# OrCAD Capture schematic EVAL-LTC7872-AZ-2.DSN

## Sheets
1 PAGE1: size C; note: HIGH POWER POLY-PHASE BI-DIRECTIONAL SUPPLY/CHARGER
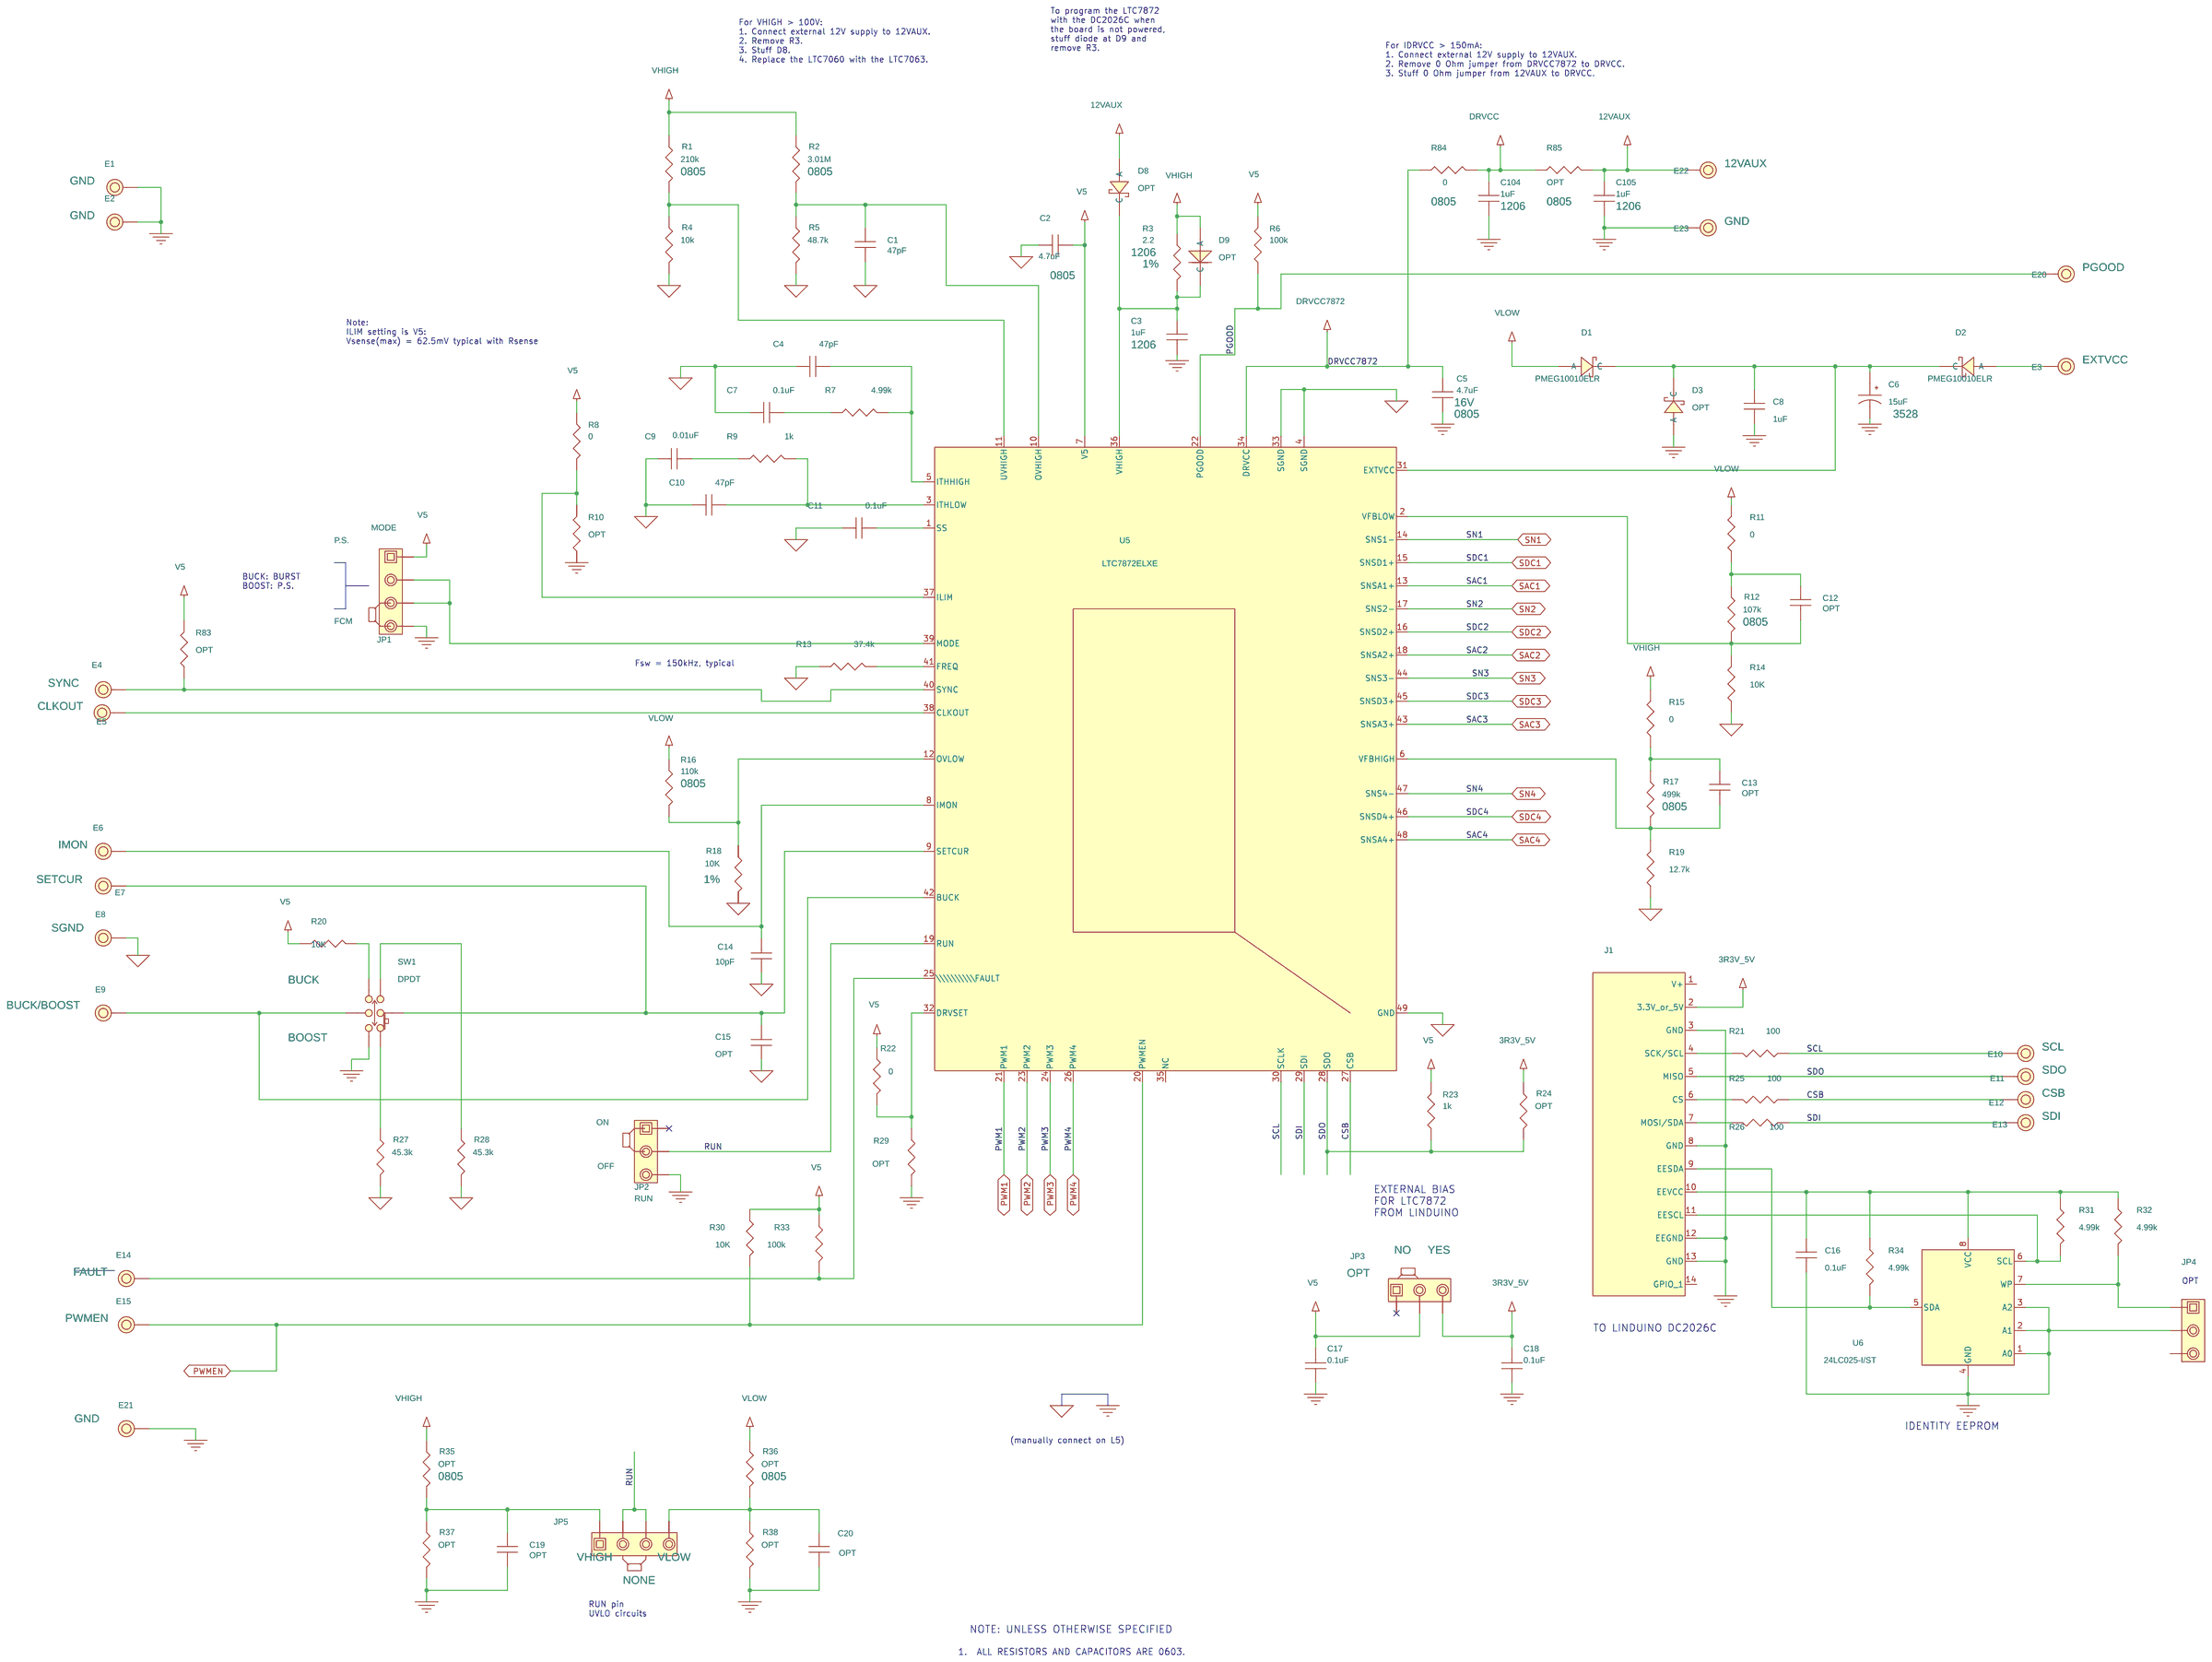
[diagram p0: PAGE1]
2 PAGE2: size Custom
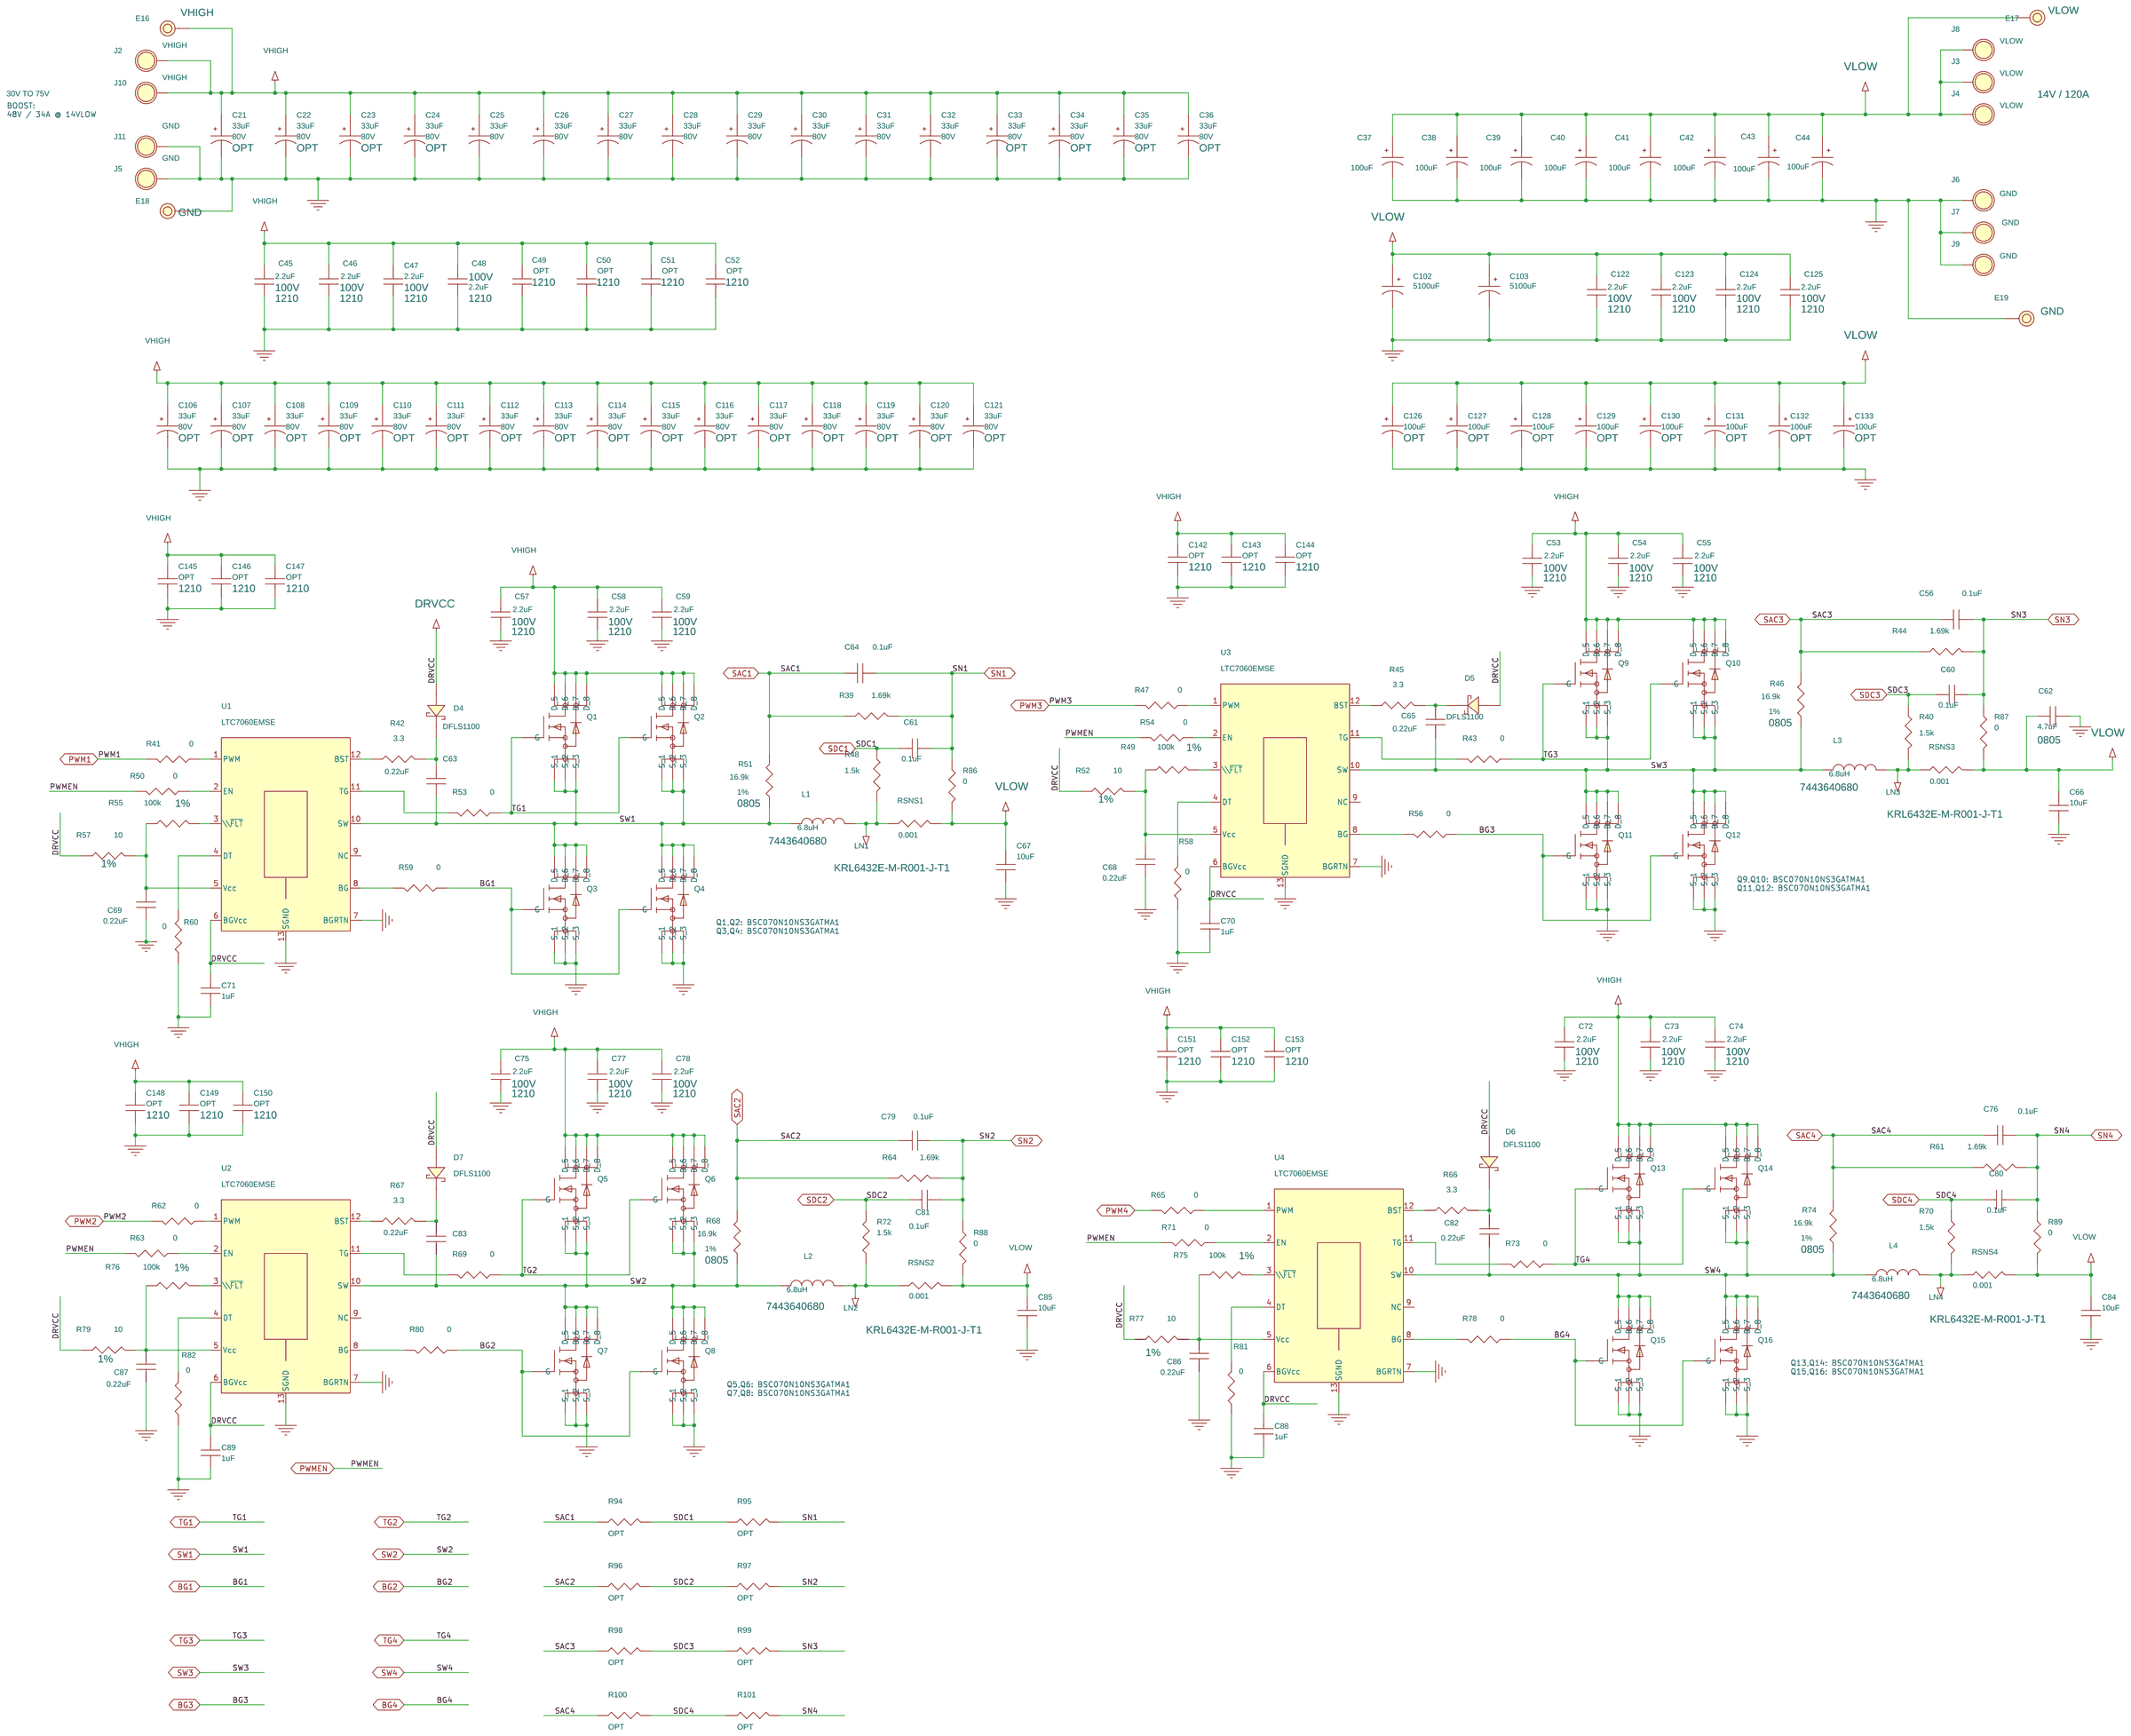
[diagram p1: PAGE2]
3 PAGE3: size B
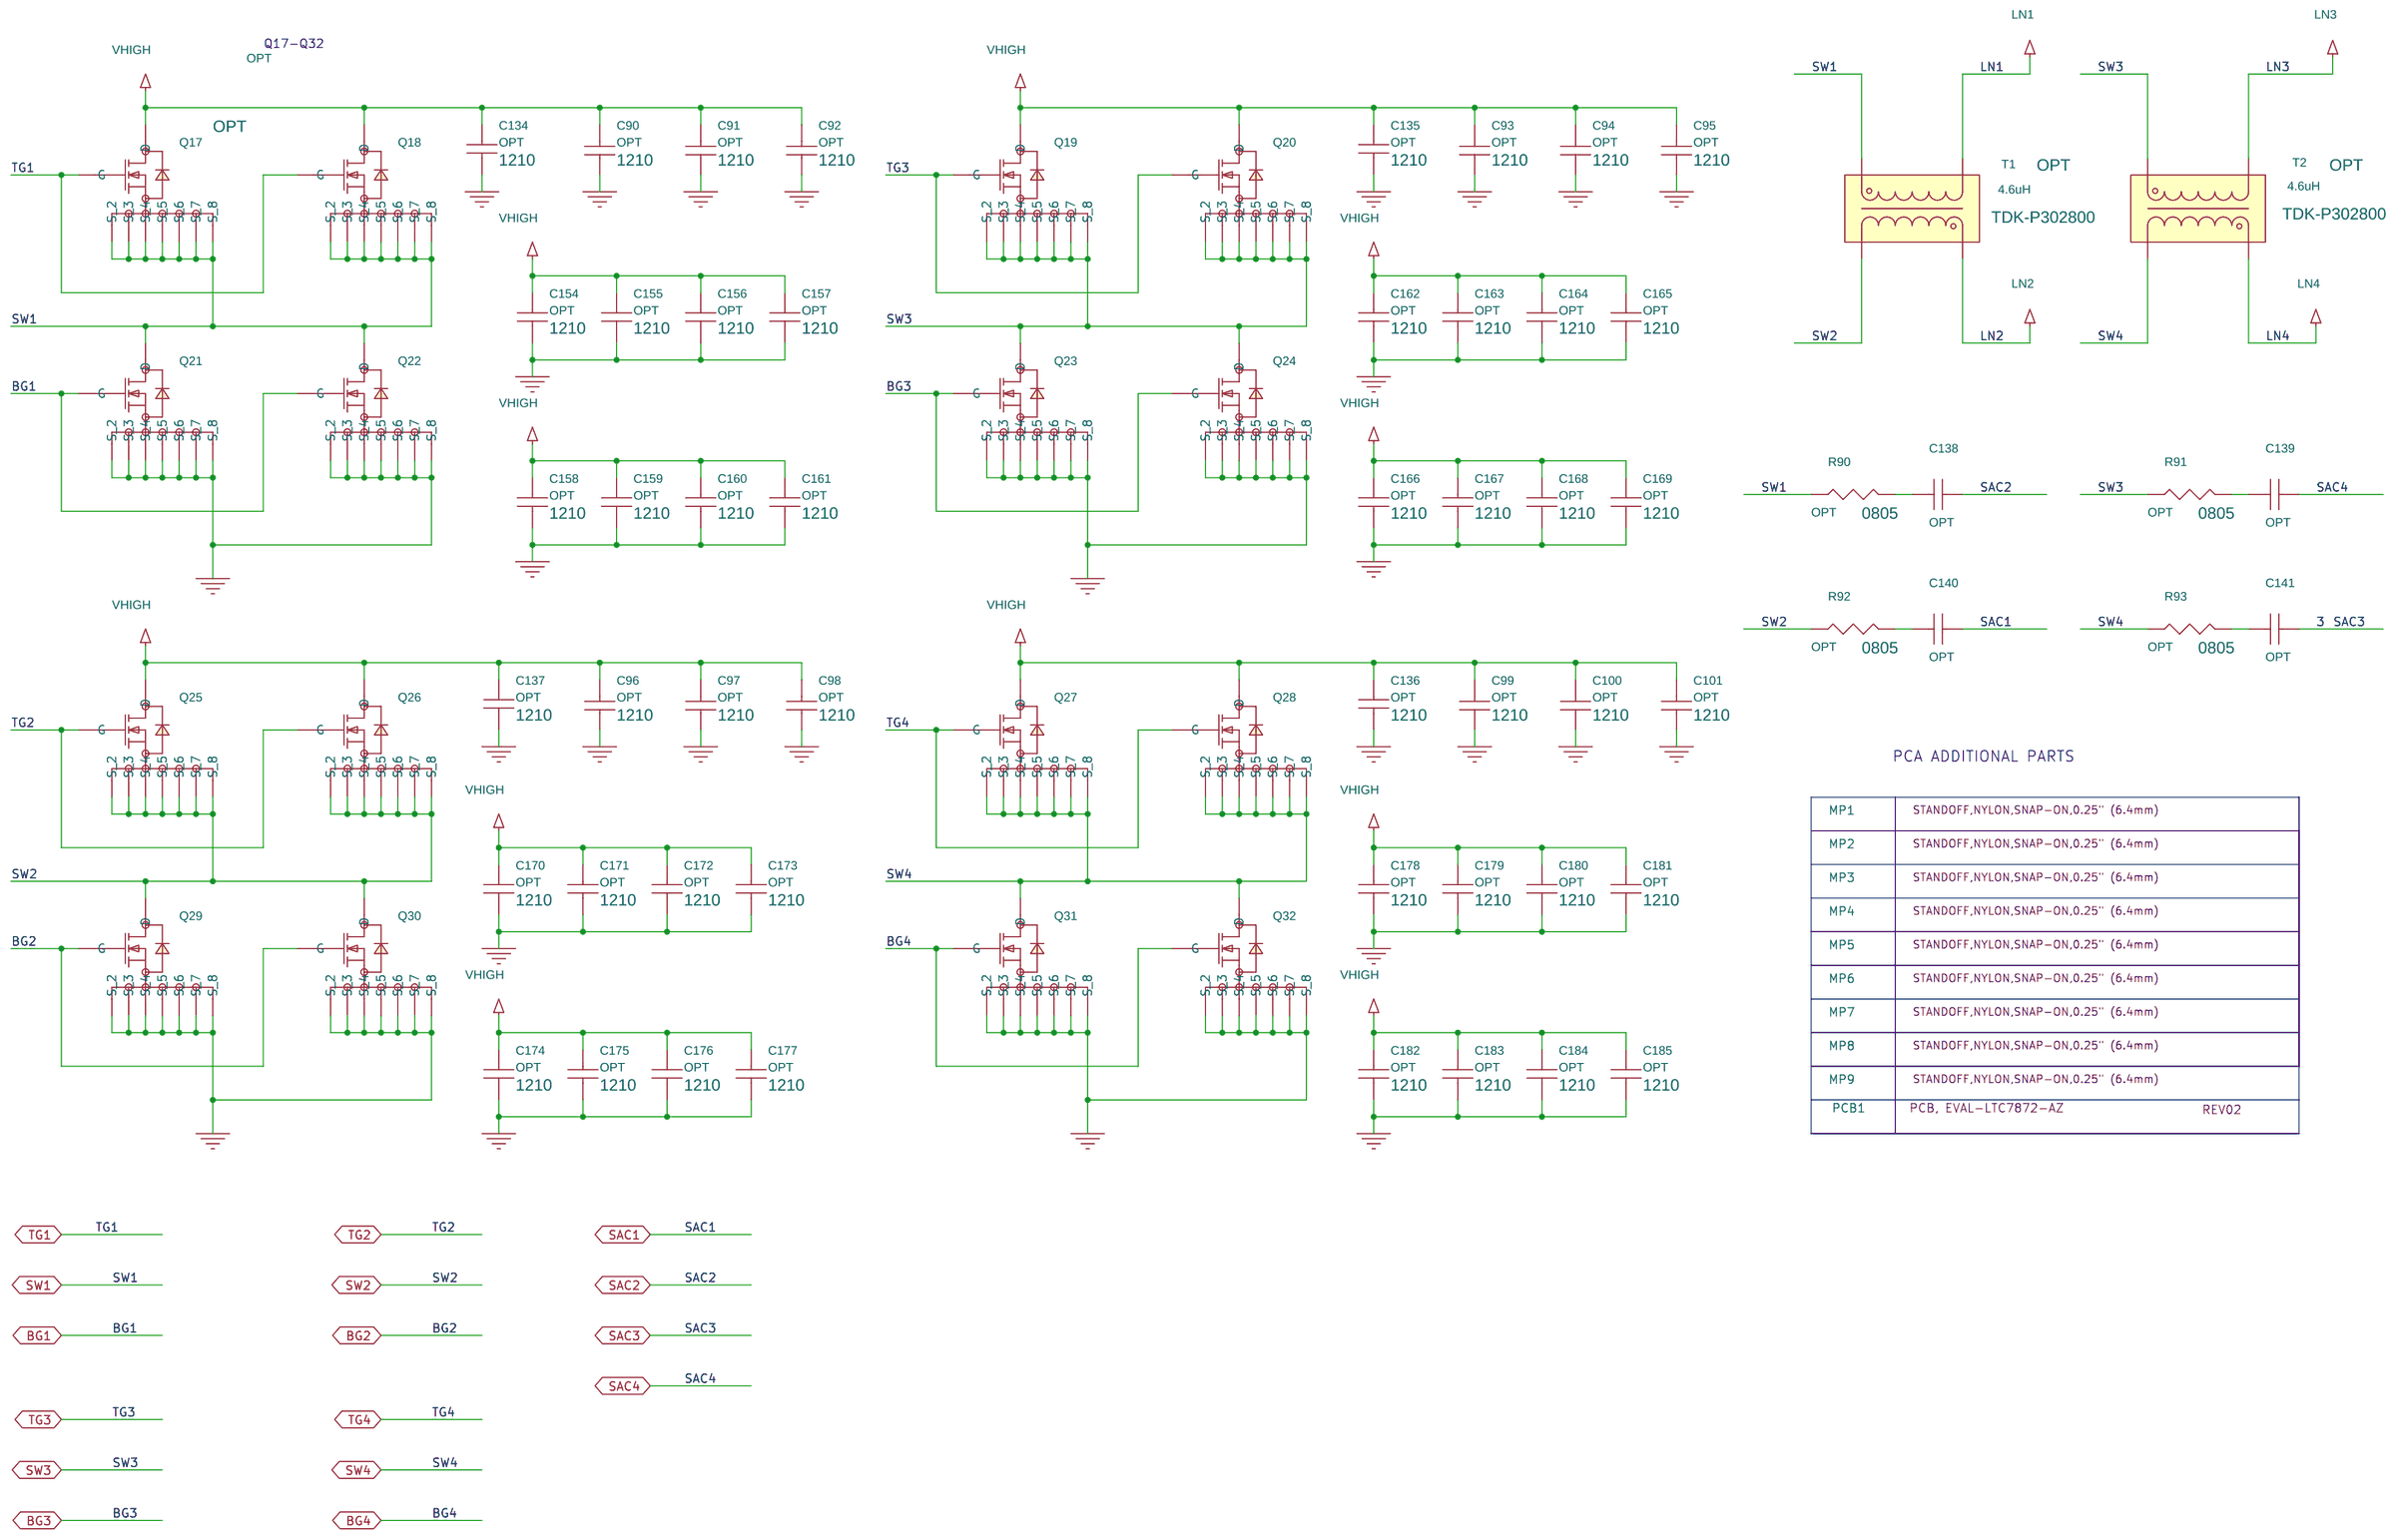
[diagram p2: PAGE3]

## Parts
sheet PAGE1
C1  47pF  [CC0603N]
C2  4.7uF  [CC0805N]
C3  1uF  [CC1206N]
C4  47pF  [CC0603N]
C5  4.7uF  [CC0805N]
C6  15uF  [CAPMP3528N]
C7  0.1uF  [CC0603N]
C8  1uF  [CC0603N]
C9  0.01uF  [CC0603N]
C10  47pF  [CC0603N]
C11  0.1uF  [CC0603N]
C12  OPT  [CC0603N]
C13  OPT  [CC0603N]
C14  10pF  [CC0603N]
C15  OPT  [CC0603N]
C16  0.1uF  [CC0603N]
C17  0.1uF  [CC0603N]
C18  0.1uF  [CC0603N]
C19  OPT  [CC0603N]
C20  OPT  [CC0603N]
C104  1uF  [CC1206N]
C105  1uF  [CC1206N]
D1  PMEG10010ELR  [NXP-SOD-123W]
D2  PMEG10010ELR  [NXP-SOD-123W]
D3  OPT  [SOD-323F-N]
D8  OPT  [SOD-323F-N]
D9  OPT  [SOD-123N]
E1  TEST POINT  [MILLMAX2501]
E2  TEST POINT  [MILLMAX2501]
E3  TEST POINT  [MILLMAX2501]
E4  TEST POINT  [MILLMAX2501]
E5  TEST POINT  [MILLMAX2501]
E6  TEST POINT  [MILLMAX2501]
E7  TEST POINT  [MILLMAX2501]
E8  TEST POINT  [MILLMAX2501]
E9  TEST POINT  [MILLMAX2501]
E10  TEST POINT  [MILLMAX2501]
E11  TEST POINT  [MILLMAX2501]
E12  TEST POINT  [MILLMAX2501]
E13  TEST POINT  [MILLMAX2501]
E14  TEST POINT  [MILLMAX2501]
E15  TEST POINT  [MILLMAX2501]
E20  TEST POINT  [MILLMAX2501]
E21  TEST POINT  [MILLMAX2501]
E22  TEST POINT  [MILLMAX2501]
E23  TEST POINT  [MILLMAX2501]
J1  HDR,SHROUDED  [HD2X7-079-MOLEX]
JP1  HDR  [HD1X4-079]
JP2  HDR  [HD1X3-079]
JP3  OPT  [HD1X3-079]
JP4  HDR  [HD1X3-079]
JP5  HDR  [HD1X4-079]
R1  210k  [CR0805N]
R2  3.01M  [CR0805N]
R3  2.2  [CR1206N]
R4  10k  [CR0603N]
R5  48.7k  [CR0603N]
R6  100k  [CR0603N]
R7  4.99k  [CR0603N]
R8  0  [CR0603N]
R9  1k  [CR0603N]
R10  OPT  [CR0603N]
R11  0  [CR0603N]
R12  107k  [CR0805N]
R13  37.4k  [CR0603N]
R14  10K  [CR0603N]
R15  0  [CR0603N]
R16  110k  [CR0805N]
R17  499k  [CR0805N]
R18  10K  [CR0603N]
R19  12.7k  [CR0603N]
R20  10K  [CR0603N]
R21  100  [CR0603N]
R22  0  [CR0603N]
R23  1k  [CR0603N]
R24  OPT  [CR0603N]
R25  100  [CR0603N]
R26  100  [CR0603N]
R27  45.3k  [CR0603N]
R28  45.3k  [CR0603N]
R29  OPT  [CR0603N]
R30  10K  [CR0603N]
R31  4.99k  [CR0603N]
R32  4.99k  [CR0603N]
R33  100k  [CR0603N]
R34  4.99k  [CR0603N]
R35  OPT  [CR0805N]
R36  OPT  [CR0805N]
R37  OPT  [CR0603N]
R38  OPT  [CR0603N]
R83  OPT  [CR0603N]
R84  0  [CR0805N]
R85  OPT  [CR0805N]
SW1  DPDT  [CK-JS202011CQN]
U5  LTC7872ELXE  [LXE-LQFP-48-1832]
U6  24LC025-I/ST  [MO-153AA_N]
XJP1  SHUNT  [SAMTEC-SHUNT-079]
XJP2  SHUNT  [SAMTEC-SHUNT-079]
XJP3  SHUNT  [SAMTEC-SHUNT-079]
XJP5  SHUNT  [SAMTEC-SHUNT-079]
sheet PAGE2
C21  33uF  [PANASONIC_ZC_10X10.2]
C22  33uF  [PANASONIC_ZC_10X10.2]
C23  33uF  [PANASONIC_ZC_10X10.2]
C24  33uF  [PANASONIC_ZC_10X10.2]
C25  33uF  [PANASONIC_ZC_10X10.2]
C26  33uF  [PANASONIC_ZC_10X10.2]
C27  33uF  [PANASONIC_ZC_10X10.2]
C28  33uF  [PANASONIC_ZC_10X10.2]
C29  33uF  [PANASONIC_ZC_10X10.2]
C30  33uF  [PANASONIC_ZC_10X10.2]
C31  33uF  [PANASONIC_ZC_10X10.2]
C32  33uF  [PANASONIC_ZC_10X10.2]
C33  33uF  [PANASONIC_ZC_10X10.2]
C34  33uF  [PANASONIC_ZC_10X10.2]
C35  33uF  [PANASONIC_ZC_10X10.2]
C36  33uF  [PANASONIC_ZC_10X10.2]
C37  100uF  [PANASONIC_ZA_6.3X7.7]
C38  100uF  [PANASONIC_ZA_6.3X7.7]
C39  100uF  [PANASONIC_ZA_6.3X7.7]
C40  100uF  [PANASONIC_ZA_6.3X7.7]
C41  100uF  [PANASONIC_ZA_6.3X7.7]
C42  100uF  [PANASONIC_ZA_6.3X7.7]
C43  100uF  [PANASONIC_ZA_6.3X7.7]
C44  100uF  [PANASONIC_ZA_6.3X7.7]
C45  2.2uF  [CC1210N]
C46  2.2uF  [CC1210N]
C47  2.2uF  [CC1210N]
C48  2.2uF  [CC1210N]
C49  OPT  [CC1210N]
C50  OPT  [CC1210N]
C51  OPT  [CC1210N]
C52  OPT  [CC1210N]
C53  2.2uF  [CC1210N]
C54  2.2uF  [CC1210N]
C55  2.2uF  [CC1210N]
C56  0.1uF  [CC0603N]
C57  2.2uF  [CC1210N]
C58  2.2uF  [CC1210N]
C59  2.2uF  [CC1210N]
C60  0.1uF  [CC0603N]
C61  0.1uF  [CC0603N]
C62  4.7uF  [CC0805N]
C63  0.22uF  [CC0603N]
C64  0.1uF  [CC0603N]
C65  0.22uF  [CC0603N]
C66  10uF  [CC1210N]
C67  10uF  [CC1210N]
C68  0.22uF  [CC0603N]
C69  0.22uF  [CC0603N]
C70  1uF  [CC0603N]
C71  1uF  [CC0603N]
C72  2.2uF  [CC1210N]
C73  2.2uF  [CC1210N]
C74  2.2uF  [CC1210N]
C75  2.2uF  [CC1210N]
C76  0.1uF  [CC0603N]
C77  2.2uF  [CC1210N]
C78  2.2uF  [CC1210N]
C79  0.1uF  [CC0603N]
C80  0.1uF  [CC0603N]
C81  0.1uF  [CC0603N]
C82  0.22uF  [CC0603N]
C83  0.22uF  [CC0603N]
C84  10uF  [CC1210N]
C85  10uF  [CC1210N]
C86  0.22uF  [CC0603N]
C87  0.22uF  [CC0603N]
C88  1uF  [CC0603N]
C89  1uF  [CC0603N]
C102  5100uF  [Chemi_18x30]
C103  5100uF  [Chemi_18x30]
C106  33uF  [PANASONIC_ZC_10X10.2]
C107  33uF  [PANASONIC_ZC_10X10.2]
C108  33uF  [PANASONIC_ZC_10X10.2]
C109  33uF  [PANASONIC_ZC_10X10.2]
C110  33uF  [PANASONIC_ZC_10X10.2]
C111  33uF  [PANASONIC_ZC_10X10.2]
C112  33uF  [PANASONIC_ZC_10X10.2]
C113  33uF  [PANASONIC_ZC_10X10.2]
C114  33uF  [PANASONIC_ZC_10X10.2]
C115  33uF  [PANASONIC_ZC_10X10.2]
C116  33uF  [PANASONIC_ZC_10X10.2]
C117  33uF  [PANASONIC_ZC_10X10.2]
C118  33uF  [PANASONIC_ZC_10X10.2]
C119  33uF  [PANASONIC_ZC_10X10.2]
C120  33uF  [PANASONIC_ZC_10X10.2]
C121  33uF  [PANASONIC_ZC_10X10.2]
C122  2.2uF  [CC1210N]
C123  2.2uF  [CC1210N]
C124  2.2uF  [CC1210N]
C125  2.2uF  [CC1210N]
C126  100uF  [PANASONIC_ZA_6.3X7.7]
C127  100uF  [PANASONIC_ZA_6.3X7.7]
C128  100uF  [PANASONIC_ZA_6.3X7.7]
C129  100uF  [PANASONIC_ZA_6.3X7.7]
C130  100uF  [PANASONIC_ZA_6.3X7.7]
C131  100uF  [PANASONIC_ZA_6.3X7.7]
C132  100uF  [PANASONIC_ZA_6.3X7.7]
C133  100uF  [PANASONIC_ZA_6.3X7.7]
C142  OPT  [CC1210N]
C143  OPT  [CC1210N]
C144  OPT  [CC1210N]
C145  OPT  [CC1210N]
C146  OPT  [CC1210N]
C147  OPT  [CC1210N]
C148  OPT  [CC1210N]
C149  OPT  [CC1210N]
C150  OPT  [CC1210N]
C151  OPT  [CC1210N]
C152  OPT  [CC1210N]
C153  OPT  [CC1210N]
D4  DFLS1100  [POWERDI-123]
D5  DFLS1100  [POWERDI-123]
D6  DFLS1100  [POWERDI-123]
D7  DFLS1100  [POWERDI-123]
E16  TEST POINT  [MILLMAX2501]
E17  TEST POINT  [MILLMAX2501]
E18  TEST POINT  [MILLMAX2501]
E19  TEST POINT  [MILLMAX2501]
J2  STUD,#10-32  [PENN-KFH-032]
J3  STUD,#10-32  [PENN-KFH-032]
J4  STUD,#10-32  [PENN-KFH-032]
J5  STUD,#10-32  [PENN-KFH-032]
J6  STUD,#10-32  [PENN-KFH-032]
J7  STUD,#10-32  [PENN-KFH-032]
J8  STUD,#10-32  [PENN-KFH-032]
J9  STUD,#10-32  [PENN-KFH-032]
J10  STUD,#10-32  [PENN-KFH-032]
J11  STUD,#10-32  [PENN-KFH-032]
L1  6.8uH  [WURTH-2818]
L2  6.8uH  [WURTH-2818]
L3  6.8uH  [WURTH-2818]
L4  6.8uH  [WURTH-2818]
Q1  BSC070N10NS3GATMA1  [INFINEON-PG-TDSON-8]
Q2  BSC070N10NS3GATMA1  [INFINEON-PG-TDSON-8]
Q3  BSC070N10NS3GATMA1  [INFINEON-PG-TDSON-8]
Q4  BSC070N10NS3GATMA1  [INFINEON-PG-TDSON-8]
Q5  BSC070N10NS3GATMA1  [INFINEON-PG-TDSON-8]
Q6  BSC070N10NS3GATMA1  [INFINEON-PG-TDSON-8]
Q7  BSC070N10NS3GATMA1  [INFINEON-PG-TDSON-8]
Q8  BSC070N10NS3GATMA1  [INFINEON-PG-TDSON-8]
Q9  BSC070N10NS3GATMA1  [INFINEON-PG-TDSON-8]
Q10  BSC070N10NS3GATMA1  [INFINEON-PG-TDSON-8]
Q11  BSC070N10NS3GATMA1  [INFINEON-PG-TDSON-8]
Q12  BSC070N10NS3GATMA1  [INFINEON-PG-TDSON-8]
Q13  BSC070N10NS3GATMA1  [INFINEON-PG-TDSON-8]
Q14  BSC070N10NS3GATMA1  [INFINEON-PG-TDSON-8]
Q15  BSC070N10NS3GATMA1  [INFINEON-PG-TDSON-8]
Q16  BSC070N10NS3GATMA1  [INFINEON-PG-TDSON-8]
R39  1.69k  [CR0603N]
R40  1.5k  [CR0603N]
R41  0  [CR0603N]
R42  3.3  [CR0603N]
R43  0  [CR0603N]
R44  1.69k  [CR0603N]
R45  3.3  [CR0603N]
R46  16.9k  [CR0805N]
R47  0  [CR0603N]
R48  1.5k  [CR0603N]
R49  100k  [CR0603N]
R50  0  [CR0603N]
R51  16.9k  [CR0805N]
R52  10  [CR0603N]
R53  0  [CR0603N]
R54  0  [CR0603N]
R55  100k  [CR0603N]
R56  0  [CR0603N]
R57  10  [CR0603N]
R58  0  [CR0603N]
R59  0  [CR0603N]
R60  0  [CR0603N]
R61  1.69k  [CR0603N]
R62  0  [CR0603N]
R63  0  [CR0603N]
R64  1.69k  [CR0603N]
R65  0  [CR0603N]
R66  3.3  [CR0603N]
R67  3.3  [CR0603N]
R68  16.9k  [CR0805N]
R69  0  [CR0603N]
R70  1.5k  [CR0603N]
R71  0  [CR0603N]
R72  1.5k  [CR0603N]
R73  0  [CR0603N]
R74  16.9k  [CR0805N]
R75  100k  [CR0603N]
R76  100k  [CR0603N]
R77  10  [CR0603N]
R78  0  [CR0603N]
R79  10  [CR0603N]
R80  0  [CR0603N]
R81  0  [CR0603N]
R82  0  [CR0603N]
R86  0  [CR0603N]
R87  0  [CR0603N]
R88  0  [CR0603N]
R89  0  [CR0603N]
R94  OPT  [CR0603N]
R95  OPT  [CR0603N]
R96  OPT  [CR0603N]
R97  OPT  [CR0603N]
R98  OPT  [CR0603N]
R99  OPT  [CR0603N]
R100  OPT  [CR0603N]
R101  OPT  [CR0603N]
RSNS1  0.001  [SUSUMU-KRL6432]
RSNS2  0.001  [SUSUMU-KRL6432]
RSNS3  0.001  [SUSUMU-KRL6432]
RSNS4  0.001  [SUSUMU-KRL6432]
U1  LTC7060EMSE  [LTC-MSE-12-1666]
U2  LTC7060EMSE  [LTC-MSE-12-1666]
U3  LTC7060EMSE  [LTC-MSE-12-1666]
U4  LTC7060EMSE  [LTC-MSE-12-1666]
sheet PAGE3
C90  OPT  [CC1210N]
C91  OPT  [CC1210N]
C92  OPT  [CC1210N]
C93  OPT  [CC1210N]
C94  OPT  [CC1210N]
C95  OPT  [CC1210N]
C96  OPT  [CC1210N]
C97  OPT  [CC1210N]
C98  OPT  [CC1210N]
C99  OPT  [CC1210N]
C100  OPT  [CC1210N]
C101  OPT  [CC1210N]
C134  OPT  [CC1210N]
C135  OPT  [CC1210N]
C136  OPT  [CC1210N]
C137  OPT  [CC1210N]
C138  OPT  [CC0603N]
C139  OPT  [CC0603N]
C140  OPT  [CC0603N]
C141  OPT  [CC0603N]
C154  OPT  [CC1210N]
C155  OPT  [CC1210N]
C156  OPT  [CC1210N]
C157  OPT  [CC1210N]
C158  OPT  [CC1210N]
C159  OPT  [CC1210N]
C160  OPT  [CC1210N]
C161  OPT  [CC1210N]
C162  OPT  [CC1210N]
C163  OPT  [CC1210N]
C164  OPT  [CC1210N]
C165  OPT  [CC1210N]
C166  OPT  [CC1210N]
C167  OPT  [CC1210N]
C168  OPT  [CC1210N]
C169  OPT  [CC1210N]
C170  OPT  [CC1210N]
C171  OPT  [CC1210N]
C172  OPT  [CC1210N]
C173  OPT  [CC1210N]
C174  OPT  [CC1210N]
C175  OPT  [CC1210N]
C176  OPT  [CC1210N]
C177  OPT  [CC1210N]
C178  OPT  [CC1210N]
C179  OPT  [CC1210N]
C180  OPT  [CC1210N]
C181  OPT  [CC1210N]
C182  OPT  [CC1210N]
C183  OPT  [CC1210N]
C184  OPT  [CC1210N]
C185  OPT  [CC1210N]
MP1  STANDOFF  [MTG-8831]
MP2  STANDOFF  [MTG-8831]
MP3  STANDOFF  [MTG-8831]
MP4  STANDOFF  [MTG-8831]
MP5  STANDOFF  [MTG-8831]
MP6  STANDOFF  [MTG-8831]
MP7  STANDOFF  [MTG-8831]
MP8  STANDOFF  [MTG-8831]
MP9  STANDOFF  [MTG-8831]
PCB1  PCB, EVAL-LTC7872-AZ
Q17  OPT  [INFINEON-PG-HSOF-8-1]
Q18  OPT  [INFINEON-PG-HSOF-8-1]
Q19  OPT  [INFINEON-PG-HSOF-8-1]
Q20  OPT  [INFINEON-PG-HSOF-8-1]
Q21  OPT  [INFINEON-PG-HSOF-8-1]
Q22  OPT  [INFINEON-PG-HSOF-8-1]
Q23  OPT  [INFINEON-PG-HSOF-8-1]
Q24  OPT  [INFINEON-PG-HSOF-8-1]
Q25  OPT  [INFINEON-PG-HSOF-8-1]
Q26  OPT  [INFINEON-PG-HSOF-8-1]
Q27  OPT  [INFINEON-PG-HSOF-8-1]
Q28  OPT  [INFINEON-PG-HSOF-8-1]
Q29  OPT  [INFINEON-PG-HSOF-8-1]
Q30  OPT  [INFINEON-PG-HSOF-8-1]
Q31  OPT  [INFINEON-PG-HSOF-8-1]
Q32  OPT  [INFINEON-PG-HSOF-8-1]
R90  OPT  [CR0805N]
R91  OPT  [CR0805N]
R92  OPT  [CR0805N]
R93  OPT  [CR0805N]
T1  4.6uH  [TDK-P302800]
T2  4.6uH  [TDK-P302800]

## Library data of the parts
C1 C4 C10 = CAP: CAP.,47pF,C0G,50V,5%,0603; CLASS: DISCRETE; Dielectric Type: C0G; FPLIST: CC0603N,CC0603L,CC0603M; Inventory Qty: 42680; Manufacturer: MURATA; Manufacturer PN: GRM1885C1H470JA01D; PART_NUMBER: 150-0054; Package Size: 0603; Rated Voltage: 50V; Tolerance: 5%
C2 C5 C62 = CAP: CAP.,4.7uF,X7R,16V,10%,0805; CLASS: DISCRETE; Dielectric Type: X7R; FPLIST: CC0805N,CC0805L,CC0805M; Inventory Qty: 55340; Manufacturer: AVX; Manufacturer PN: 0805YC475KAT2A; PART_NUMBER: 150-2085; Package Size: 0805; Part Number: AVX 0805YC475KAT2A; Rated Voltage: 16V; Tolerance: 10%
C3 C104 C105 = CAP: CAP.,1uF,X7R,100V,10%,1206; CLASS: DISCRETE; Dielectric Type: X7R; FPLIST: CC1206N,CC1206L,CC1206M; Inventory Qty: 11126; Manufacturer: AVX; Manufacturer PN: 12061C105KAT2A; PART_NUMBER: 150-3438; Package Size: 1206; Rated Voltage: 100V; Tolerance: 10%
C6 = CAP_P_ALT: CAP.,15uF,TANT,16V,20%,3528; CLASS: DISCRETE; Dielectric Type: TANT; FPLIST: CAPMP3528N,CAPMP3528L,CAPMP3528M; Inventory Qty: 1000; Manufacturer: KEMET; Manufacturer PN: T521B156M016ATE090; PART_NUMBER: 150-0768; Package Size: 3528; Rated Voltage: 16V; Tolerance: 20%
C7 C11 C17 C18 = CAP: CAP.,0.1uF,X7R,16V,10%,0603; CLASS: DISCRETE; Dielectric Type: X7R; FPLIST: CC0603N,CC0603L,CC0603M; Inventory Qty: 98540; Manufacturer: AVX; Manufacturer PN: 0603YC104KAT2A; PART_NUMBER: 150-0164; Package Size: 0603; Package Type: SMD; Rated Voltage: 16V; Tolerance: 10%
C8 = CAP: CAP.,1uF,X7R,25V,10%,0603,AEC-Q200; CLASS: DISCRETE; Dielectric Type: X7R; FPLIST: CC0603N,CC0603L,CC0603M; Inventory Qty: 53700; Manufacturer: MURATA; Manufacturer PN: GCM188R71E105KA64D; PART_NUMBER: 150-0291; Package Size: 0603; Part Number: MURATA GRM188R71E105KA12D; Rated Voltage: 25V; Tolerance: 10%
C9 = CAP: CAP.,0.01uF,X7R,16V,10%,0603; CLASS: DISCRETE; Dielectric Type: X7R; FPLIST: CC0603N,CC0603L,CC0603M; Inventory Qty: 67002; Manufacturer: AVX; Manufacturer PN: 0603YC103KAT2A; PART_NUMBER: 150-0038; Package Size: 0603; Rated Voltage: 16V; Tolerance: 10%
C12 C13 C19 C20 = CAP: CAP., OPTION, 0603; CLASS: DISCRETE; FPLIST: CC0603N,CC0603L,CC0603M; PART_NUMBER: 150-3038; Package Size: 0603; Package Type: SMD
C14 = CAP: CAP.,10pF,C0G,100V,+/-0.1pF,0603; CLASS: DISCRETE; Dielectric Type: C0G; FPLIST: CC0603N,CC0603L,CC0603M; Inventory Qty: 190; Manufacturer: AVX; Manufacturer PN: 06031A100BAT2A; PART_NUMBER: 150-2528; Package Size: 0603; Part Number: AVX 06031A100KAT2A / AVX; Rated Voltage: 100V; Tolerance: +/-0.1pF
C15 C138-C141 = CAP: CAP., OPTION, 0603; CLASS: DISCRETE; FPLIST: CC0603N,CC0603L,CC0603M; PART_NUMBER: 150-3038; Package Size: 0603; Package Type: SMD; Part Number: AVX 06031A100KAT2A / AVX
C16 = CAP: CAP.,0.1uF,X7R,25V,10%,0603,AEC-Q200; CLASS: DISCRETE; Dielectric Type: X7R; FPLIST: CC0603N,CC0603L,CC0603M; Inventory Qty: 5452; Manufacturer: AVX; Manufacturer PN: 06033C104K4T4A; PART_NUMBER: 150-0439; Package Size: 0603; Rated Voltage: 25V; Tolerance: 10%
D1 D2 = DIODE_SCHOTTKY_A: DIODE,SCHOTTKY,100V,1A,SOD-123W,AEC-Q101; CLASS: DISCRETE; Inventory Qty: 3150; Manufacturer: NEXPERIA; PART_NUMBER: 210-0325; Package Type: SOD-123W; Rated Voltage or Zener Voltage: 100V
D3 D8 = DIODE_SCHOTTKY_A: DIODE,OPTION, SOD-323F; CLASS: DISCRETE; FPLIST: SOD-323F-N,SOD-323F-L,SOD-323F-M; PART_NUMBER: 210-0458; Package Size: SOD-323F; Package Type: SOD323F-2
D9 = DIODE_A: DIODE, OPTION, SOD-123; CLASS: DISCRETE; FPLIST: SOD-123N,SOD-123L,SOD-123M; PART_NUMBER: 210-0115; Package Type: SOD-123
E1 E2 E18 E19 E21 E23 = TESTPOINT_.219_MILL-MAX_2501: TEST POINT,TURRET,0.094" MTG. HOLE,PCB 0.062" THK; CLASS: IO; FPLIST: MILLMAX2501,MILLMAX2501_ALT1; Inventory Qty: 823526; Manufacturer: MILL-MAX; Manufacturer PN: 2501-2-00-80-00-00-07-0; PART_FIELD_01: GND; PART_NUMBER: 260-0003; Part Number: MIIL-MAX 2501-2-00-80-00-00-07-0
E3 = TESTPOINT_.219_MILL-MAX_2501: TEST POINT,TURRET,0.094" MTG. HOLE,PCB 0.062" THK; CLASS: IO; FPLIST: MILLMAX2501,MILLMAX2501_ALT1; Inventory Qty: 823526; Manufacturer: MILL-MAX; Manufacturer PN: 2501-2-00-80-00-00-07-0; PART_FIELD_01: EXTVCC; PART_NUMBER: 260-0003; Part Number: MIIL-MAX 2501-2-00-80-00-00-07-0
E4 = TESTPOINT_.219_MILL-MAX_2501: TEST POINT,TURRET,0.094" MTG. HOLE,PCB 0.062" THK; CLASS: IO; FPLIST: MILLMAX2501,MILLMAX2501_ALT1; Inventory Qty: 823526; Manufacturer: MILL-MAX; Manufacturer PN: 2501-2-00-80-00-00-07-0; PART_FIELD_01: SYNC; PART_NUMBER: 260-0003; Part Number: MIIL-MAX 2501-2-00-80-00-00-07-0
E5 = TESTPOINT_.219_MILL-MAX_2501: TEST POINT,TURRET,0.094" MTG. HOLE,PCB 0.062" THK; CLASS: IO; FPLIST: MILLMAX2501,MILLMAX2501_ALT1; Inventory Qty: 823526; Manufacturer: MILL-MAX; Manufacturer PN: 2501-2-00-80-00-00-07-0; PART_FIELD_01: CLKOUT; PART_NUMBER: 260-0003; Part Number: MIIL-MAX 2501-2-00-80-00-00-07-0
E6 = TESTPOINT_.219_MILL-MAX_2501: TEST POINT,TURRET,0.094" MTG. HOLE,PCB 0.062" THK; CLASS: IO; FPLIST: MILLMAX2501,MILLMAX2501_ALT1; Inventory Qty: 823526; Manufacturer: MILL-MAX; Manufacturer PN: 2501-2-00-80-00-00-07-0; PART_FIELD_01: IMON; PART_NUMBER: 260-0003; Part Number: MIIL-MAX 2501-2-00-80-00-00-07-0
E7 = TESTPOINT_.219_MILL-MAX_2501: TEST POINT,TURRET,0.094" MTG. HOLE,PCB 0.062" THK; CLASS: IO; FPLIST: MILLMAX2501,MILLMAX2501_ALT1; Inventory Qty: 823526; Manufacturer: MILL-MAX; Manufacturer PN: 2501-2-00-80-00-00-07-0; PART_FIELD_01: SETCUR; PART_NUMBER: 260-0003; Part Number: MIIL-MAX 2501-2-00-80-00-00-07-0
E8 = TESTPOINT_.219_MILL-MAX_2501: TEST POINT,TURRET,0.094" MTG. HOLE,PCB 0.062" THK; CLASS: IO; FPLIST: MILLMAX2501,MILLMAX2501_ALT1; Inventory Qty: 823526; Manufacturer: MILL-MAX; Manufacturer PN: 2501-2-00-80-00-00-07-0; PART_FIELD_01: SGND; PART_NUMBER: 260-0003; Part Number: MIIL-MAX 2501-2-00-80-00-00-07-0
E9 = TESTPOINT_.219_MILL-MAX_2501: TEST POINT,TURRET,0.094" MTG. HOLE,PCB 0.062" THK; CLASS: IO; FPLIST: MILLMAX2501,MILLMAX2501_ALT1; Inventory Qty: 823526; Manufacturer: MILL-MAX; Manufacturer PN: 2501-2-00-80-00-00-07-0; PART_FIELD_01: BUCK/BOOST; PART_NUMBER: 260-0003; Part Number: MIIL-MAX 2501-2-00-80-00-00-07-0
E10 = TESTPOINT_.219_MILL-MAX_2501: TEST POINT,TURRET,0.094" MTG. HOLE,PCB 0.062" THK; CLASS: IO; FPLIST: MILLMAX2501,MILLMAX2501_ALT1; Inventory Qty: 823526; Manufacturer: MILL-MAX; Manufacturer PN: 2501-2-00-80-00-00-07-0; PART_FIELD_01: SCL; PART_NUMBER: 260-0003; Part Number: MIIL-MAX 2501-2-00-80-00-00-07-0
E11 = TESTPOINT_.219_MILL-MAX_2501: TEST POINT,TURRET,0.094" MTG. HOLE,PCB 0.062" THK; CLASS: IO; FPLIST: MILLMAX2501,MILLMAX2501_ALT1; Inventory Qty: 823526; Manufacturer: MILL-MAX; Manufacturer PN: 2501-2-00-80-00-00-07-0; PART_FIELD_01: SDO; PART_NUMBER: 260-0003; Part Number: MIIL-MAX 2501-2-00-80-00-00-07-0
E12 = TESTPOINT_.219_MILL-MAX_2501: TEST POINT,TURRET,0.094" MTG. HOLE,PCB 0.062" THK; CLASS: IO; FPLIST: MILLMAX2501,MILLMAX2501_ALT1; Inventory Qty: 823526; Manufacturer: MILL-MAX; Manufacturer PN: 2501-2-00-80-00-00-07-0; PART_FIELD_01: CSB; PART_NUMBER: 260-0003; Part Number: MIIL-MAX 2501-2-00-80-00-00-07-0
E13 = TESTPOINT_.219_MILL-MAX_2501: TEST POINT,TURRET,0.094" MTG. HOLE,PCB 0.062" THK; CLASS: IO; FPLIST: MILLMAX2501,MILLMAX2501_ALT1; Inventory Qty: 823526; Manufacturer: MILL-MAX; Manufacturer PN: 2501-2-00-80-00-00-07-0; PART_FIELD_01: SDI; PART_NUMBER: 260-0003; Part Number: MIIL-MAX 2501-2-00-80-00-00-07-0
E14 = TESTPOINT_.219_MILL-MAX_2501: TEST POINT,TURRET,0.094" MTG. HOLE,PCB 0.062" THK; CLASS: IO; FPLIST: MILLMAX2501,MILLMAX2501_ALT1; Inventory Qty: 823526; Manufacturer: MILL-MAX; Manufacturer PN: 2501-2-00-80-00-00-07-0; PART_FIELD_01: FAULT; PART_NUMBER: 260-0003; Part Number: MIIL-MAX 2501-2-00-80-00-00-07-0
E15 = TESTPOINT_.219_MILL-MAX_2501: TEST POINT,TURRET,0.094" MTG. HOLE,PCB 0.062" THK; CLASS: IO; FPLIST: MILLMAX2501,MILLMAX2501_ALT1; Inventory Qty: 823526; Manufacturer: MILL-MAX; Manufacturer PN: 2501-2-00-80-00-00-07-0; PART_FIELD_01: PWMEN; PART_NUMBER: 260-0003; Part Number: MIIL-MAX 2501-2-00-80-00-00-07-0
E20 = TESTPOINT_.219_MILL-MAX_2501: TEST POINT,TURRET,0.094" MTG. HOLE,PCB 0.062" THK; CLASS: IO; FPLIST: MILLMAX2501,MILLMAX2501_ALT1; Inventory Qty: 823526; Manufacturer: MILL-MAX; Manufacturer PN: 2501-2-00-80-00-00-07-0; PART_FIELD_01: PGOOD; PART_NUMBER: 260-0003; Part Number: MIIL-MAX 2501-2-00-80-00-00-07-0
E22 = TESTPOINT_.219_MILL-MAX_2501: TEST POINT,TURRET,0.094" MTG. HOLE,PCB 0.062" THK; CLASS: IO; FPLIST: MILLMAX2501,MILLMAX2501_ALT1; Inventory Qty: 823526; Manufacturer: MILL-MAX; Manufacturer PN: 2501-2-00-80-00-00-07-0; PART_FIELD_01: 12VAUX; PART_NUMBER: 260-0003; Part Number: MIIL-MAX 2501-2-00-80-00-00-07-0
J1 = DC590_ALT2: CONN.,HDR,SHROUDED,PLUG,MALE,2x7,2mm,VERT,ST,THT,KEYED; CLASS: IO; Inventory Qty: 20387; Manufacturer: MOLEX; Manufacturer PN: 87831-1420; PART_NUMBER: 250-0403
JP1 = HDR1X4_ALT1: CONN.,HDR,MALE,1x4,2mm,VERT,ST,THT; 10th Part Field: BUCK: BURST; 12th Part Field: FCM; 13tht Part Field: MODE; 9th Part Field: P.S.; CLASS: IO; Inventory Qty: 11710; Manufacturer: SULLINS CONNECTOR SOLUTIONS; Manufacturer PN: NRPN041PAEN-RC; PART_NUMBER: 250-0431
JP2 JP4 = 1X3_A: CONN.,HDR,MALE,1x3,2mm,VERT,ST,THT,NO SUBS. ALLOWED; 11th Part Field: OFF; 12th Part Field: RUN; 9th Part Field: ON; CLASS: IO; Inventory Qty: 7904; Manufacturer: SAMTEC; Manufacturer PN: TMM-103-02-L-S; PART_NUMBER: 250-0638
JP3 = 1X3_A: CONN.,HDR,MALE,1x3,2mm,VERT,ST,THT,NO SUBS. ALLOWED; 10th Part Field: YES; 11th Part Field: EXTERNAL BIAS; 12th Part Field: RUN; 9th Part Field: NO; CLASS: IO; Inventory Qty: 7904; Manufacturer: SAMTEC; Manufacturer PN: TMM-103-02-L-S; PART_NUMBER: 250-0638
JP5 = HDR1X4_ALT1: CONN.,HDR,MALE,1x4,2mm,VERT,ST,THT; 10th Part Field: VLOW; 11th Part Field: NONE; 9th Part Field: VHIGH; CLASS: IO; Inventory Qty: 11710; Manufacturer: SULLINS CONNECTOR SOLUTIONS; Manufacturer PN: NRPN041PAEN-RC; PART_NUMBER: 250-0431
R1 = RES: RES.,210k OHMS,1%,1/8W,0805,AEC-Q200; CLASS: DISCRETE; FPLIST: CR0805N,CR0805L,CR0805M; Inventory Qty: 0; Manufacturer: VISHAY; Manufacturer PN: CRCW0805210KFKEA; PART_NUMBER: 100-1643; Package Size: 0805; Rated Power: 1/8W; Temperature Coefficient: +/-100ppm; Tolerance: 1%
R2 = RES: RES.,3.01M OHMS,1%,1/8W,0805,AEC-Q200; CLASS: DISCRETE; FPLIST: CR0805N,CR0805L,CR0805M; Inventory Qty: 10000; Manufacturer: VISHAY; Manufacturer PN: CRCW08053M01FKEA; PART_NUMBER: 100-1588; Package Size: 0805; Rated Power: 1/8W; Temperature Coefficient: +/-100ppm; Tolerance: 1%
R3 = RES: RES.,2.2 OHMS,1%,1/4W,1206,AEC-Q200; CLASS: DISCRETE; FPLIST: CR1206N,CR1206L,CR1206M; Inventory Qty: 29775; Manufacturer: VISHAY; Manufacturer PN: CRCW12062R20FKEA; PART_NUMBER: 100-0778; Package Size: 1206; Part Number: VISHAY CRCW12062R20FKEA; Rated Power: 1/4W; Temperature Coefficient: 100ppm; Tolerance: 1%
R4 = RES: RES.,10k OHMS,1%,1/10W,0603; CLASS: DISCRETE; FPLIST: CR0603N,CR0603L,CR0603M; Inventory Qty: 94405; Manufacturer: VISHAY; Manufacturer PN: CRCW060310K0FKEC; PART_NUMBER: 100-2532; Package Size: 0603; Rated Power: 1/10W; Temperature Coefficient: 100ppm/C; Tolerance: 1%
R5 = RES: RES.,48.7k OHMS,1%,1/10W,0603,AEC-Q200; CLASS: DISCRETE; FPLIST: CR0603N,CR0603L,CR0603M; Inventory Qty: 18680; Manufacturer: VISHAY; Manufacturer PN: CRCW060348K7FKEA; PART_NUMBER: 100-0260; Package Size: 0603; Rated Power: 1/10W; Temperature Coefficient: 100ppm/C; Tolerance: 1%
R6 = RES: RES.,100k OHMS,1%,1/10W,0603,AEC-Q200; CLASS: DISCRETE; FPLIST: CR0603N,CR0603L,CR0603M; Inventory Qty: 185604; Manufacturer: VISHAY; Manufacturer PN: CRCW0603100KFKEA; PART_NUMBER: 100-0343; Package Size: 0603; Part Number: VISHAY CRCW06030000Z0EA; Rated Power: 1/10W; Temperature Coefficient: +/-100ppm; Tolerance: 1%
R7 R31 R32 R34 = RES: RES.,4.99k OHMS,1%,1/10W,0603; CLASS: DISCRETE; FPLIST: CR0603N,CR0603L,CR0603M; Inventory Qty: 72747; Manufacturer: PANASONIC; Manufacturer PN: ERJ3EKF4991V; PART_NUMBER: 100-0121; Package Size: 0603; Rated Power: 1/10W; Temperature Coefficient: 100ppm/C; Tolerance: 1%
R8 R22 = RES: RES.,0 OHM,1/10W,0603; CLASS: DISCRETE; FPLIST: CR0603N,CR0603L,CR0603M; Inventory Qty: 57380; Manufacturer: BOURNS; Manufacturer PN: CR0603-J/-000ELF; PART_NUMBER: 100-2621; Package Size: 0603; Part Number: OPTION; Rated Power: 1/10W
R9 R23 = RES: RES.,1k OHM,1%,1/10W,0603,AEC-Q200; CLASS: DISCRETE; FPLIST: CR0603N,CR0603L,CR0603M; Inventory Qty: 112367; Manufacturer: VISHAY; Manufacturer PN: CRCW06031K00FKEA; PART_NUMBER: 100-2422; Package Size: 0603; Rated Power: 1/10W; Temperature Coefficient: 100ppm; Tolerance: 1%
R10 R83 = RES: RES., OPTION, 0603; CLASS: DISCRETE; FPLIST: CR0603N,CR0603L,CR0603M; PART_NUMBER: 100-2374; Package Size: 0603; Part Number: VISHAY CRCW060310K0FKEA
R11 R15 R43 R53 R56 R59 R69 R73 R78 R80 R86-R89 = RES: RES.,0 OHM,1/10W,0603; CLASS: DISCRETE; FPLIST: CR0603N,CR0603L,CR0603M; Inventory Qty: 57380; Manufacturer: BOURNS; Manufacturer PN: CR0603-J/-000ELF; PART_NUMBER: 100-2621; Package Size: 0603; Part Number: VISHAY CRCW06030000Z0EA; Rated Power: 1/10W
R12 = RES: RES.,107k OHMS,1%,1/8W,0805; CLASS: DISCRETE; FPLIST: CR0805N,CR0805L,CR0805M; Inventory Qty: 15000; Manufacturer: VISHAY; Manufacturer PN: CRCW0805107KFKEA; PART_NUMBER: 100-3001; Package Size: 0805; Rated Power: 1/8W; Temperature Coefficient: +/-100PPM; Tolerance: 1%
R13 = RES: RES.,37.4k OHMS,1%,1/10W,0603,AEC-Q200; CLASS: DISCRETE; FPLIST: CR0603N,CR0603L,CR0603M; Inventory Qty: 1500; Manufacturer: PANASONIC; Manufacturer PN: ERJ-3EKF3742; PART_NUMBER: 100-0862; Package Size: 0603; Rated Power: 1/10W; Temperature Coefficient: +/-100PPM; Tolerance: 1%
R14 = RES: RES.,10K OHMS,1%,1/10W,0603,AEC-Q200; CLASS: DISCRETE; FPLIST: CR0603N,CR0603L,CR0603M; Inventory Qty: 41873; Manufacturer: PANASONIC; Manufacturer PN: ERJ3EKF1002V; PART_NUMBER: 100-0602; Package Size: 0603; Part Number: VISHAY CRCW06030000Z0EA; Rated Power: 1/10W; Temperature Coefficient: 100PPM; Tolerance: 1%
R16 = RES: RES.,110k OHMS,0.1%,1/8W,0805,METAL FILM, AEC-Q200; CLASS: DISCRETE; FPLIST: CR0805N,CR0805L,CR0805M; Inventory Qty: 2400; Manufacturer: PANASONIC; Manufacturer PN: ERA6AEB114V; PART_NUMBER: 100-1307; Package Size: 0805; Rated Power: 1/8W; Temperature Coefficient: +/-25ppm; Tolerance: 0.1%
R17 = RES: RES.,499k OHMS,1%,1/8W,0805,AEC-Q200; CLASS: DISCRETE; FPLIST: CR0805N,CR0805L,CR0805M; Inventory Qty: 34780; Manufacturer: NIC; Manufacturer PN: NRC10F4993TRF; PART_NUMBER: 100-0777; Package Size: 0805; Rated Power: 1/8W; Temperature Coefficient: 100ppm; Tolerance: 1%
R18 R20 = RES: RES.,10K OHMS,1%,1/10W,0603,AEC-Q200; CLASS: DISCRETE; FPLIST: CR0603N,CR0603L,CR0603M; Inventory Qty: 41873; Manufacturer: PANASONIC; Manufacturer PN: ERJ3EKF1002V; PART_NUMBER: 100-0602; Package Size: 0603; Part Number: VISHAY CRCW060310K0FKEA; Rated Power: 1/10W; Temperature Coefficient: 100PPM; Tolerance: 1%
R19 = RES: RES.,12.7k OHMS,1%,1/10W,0603,AEC-Q200; CLASS: DISCRETE; FPLIST: CR0603N,CR0603L,CR0603M; Inventory Qty: 8842; Manufacturer: PANASONIC; Manufacturer PN: ERJ3EKF1272V; PART_NUMBER: 100-0377; Package Size: 0603; Part Number: VISHAY CRCW06030000Z0EA; Rated Power: 1/10W; Temperature Coefficient: 100ppm/C; Tolerance: 1%
R21 R25 R26 = RES: RES.,100 OHMS,1%,1/10W,0603,AEC-Q200; CLASS: DISCRETE; FPLIST: CR0603N,CR0603L,CR0603M; Inventory Qty: 81010; Manufacturer: PANASONIC; Manufacturer PN: ERJ3EKF1000V; PART_NUMBER: 100-2586; Package Size: 0603; Part Number: OPTION; Rated Power: 1/10W; Temperature Coefficient: 100ppm; Tolerance: 1%
R24 R37 R38 R94-R101 = RES: RES., OPTION, 0603; CLASS: DISCRETE; FPLIST: CR0603N,CR0603L,CR0603M; PART_NUMBER: 100-2374; Package Size: 0603
R27 R28 = RES: RES.,45.3k OHMS,1%,1/10W,0603,AEC-Q200; CLASS: DISCRETE; FPLIST: CR0603N,CR0603L,CR0603M; Inventory Qty: 20355; Manufacturer: PANASONIC; Manufacturer PN: ERJ3EKF4532V; PART_NUMBER: 100-2684; Package Size: 0603; Rated Power: 1/10W; Temperature Coefficient: 100ppm; Tolerance: 1%
R29 = RES: RES., OPTION, 0603; CLASS: DISCRETE; FPLIST: CR0603N,CR0603L,CR0603M; PART_NUMBER: 100-2374; Package Size: 0603; Part Number: OPTION
R30 = RES: RES.,10K OHMS,1%,1/10W,0603,AEC-Q200; CLASS: DISCRETE; FPLIST: CR0603N,CR0603L,CR0603M; Inventory Qty: 41873; Manufacturer: PANASONIC; Manufacturer PN: ERJ3EKF1002V; PART_NUMBER: 100-0602; Package Size: 0603; Part Number: VISHAY CRCW0603100KJNEA; Rated Power: 1/10W; Temperature Coefficient: 100PPM; Tolerance: 1%
R33 = RES: RES.,100k OHMS,1%,1/10W,0603,AEC-Q200; CLASS: DISCRETE; FPLIST: CR0603N,CR0603L,CR0603M; Inventory Qty: 185604; Manufacturer: VISHAY; Manufacturer PN: CRCW0603100KFKEA; PART_NUMBER: 100-0343; Package Size: 0603; Part Number: VISHAY CRCW0603100KJNEA; Rated Power: 1/10W; Temperature Coefficient: +/-100ppm; Tolerance: 1%
R35 R36 R85 R90-R93 = RES: RES., OPTION, 0805; CLASS: DISCRETE; FPLIST: CR0805N,CR0805L,CR0805M; PART_NUMBER: 100-2558; Package Size: 0805
R84 = RES: RES.,0 OHM,1/8W,0805,AEC-Q200; CLASS: DISCRETE; FPLIST: CR0805N,CR0805L,CR0805M; Inventory Qty: 4162; Manufacturer: PANASONIC; Manufacturer PN: ERJ6GE0R00V; PART_NUMBER: 100-1178; Package Size: 0805; Rated Power: 1/8W
SW1 = SW-DPDT-JS202011CQN_ALT1: SWITCH,SLIDE,DPDT,0.3A,6VDC,PTH; CLASS: DISCRETE; Inventory Qty: 32171; Manufacturer: C&K; Manufacturer PN: JS202011CQN; PART_FIELD_01: BUCK; PART_FIELD_02: BOOST; PART_NUMBER: 430-0039
U5 = LTC-LWE_2: IC,HIGH POWER POLY-PHASE,BI-DIRECTIONAL SUPPLY/CHARGER; CLASS: IC; Inventory Qty: 0; Manufacturer: ANALOG DEVICES INC.; Manufacturer PN: LTC7872ELXE#PBF; PART_NUMBER: LTC7872ELXE#PBF; Package Size: 7mmx7mm; Package Type: BI-DIRECTIONAL SUPPLY/CHARGER
U6 = 24LC025-I_ST_TSSOP-8_D: IC, MEMORY,EEPROM,2Kb (256x8),TSSOP-8,400kHz; CLASS: IC; FPLIST: TSSOP-8N,TSSOP-8L,TSSOP-8M,MICROCHIP-TSSOP-8; Inventory Qty: 19510; Manufacturer: Microchip; PART_NUMBER: 380-0087; Package Size: TSSOP-8; Package Type: TSSOP-8
XJP1-XJP3 XJP5 = SHUNT_2MM: CONN.,SHUNT,FEMALE,2-POS,2mm; CLASS: MECHANICAL; Inventory Qty: 268933; Manufacturer: SAMTEC; Manufacturer PN: 2SN-BK-G; PART_NUMBER: 250-0419
C21-C24 C33-C36 C106-C121 = CAP_P_ALT: CAP.,33uF,ALUM ELECT HYB,80V,20%,10x10.2mm,SMD,RADIAL,AEC-Q200; BOM Notes: OPT; CLASS: DISCRETE; Dielectric Type: ALUM ELECT HYB; Inventory Qty: 6487; Manufacturer: PANASONIC; Manufacturer PN: EEHZC1K330P; PART_NUMBER: 150-1298; Package Size: 10x10.2mm,SMD,RADIAL; Part Number: PANASONIC EEHZC1K330P; Rated Voltage: 80V; Tolerance: 20%
C25-C32 = CAP_P_ALT: CAP.,33uF,ALUM ELECT HYB,80V,20%,10x10.2mm,SMD,RADIAL,AEC-Q200; CLASS: DISCRETE; Dielectric Type: ALUM ELECT HYB; Inventory Qty: 6487; Manufacturer: PANASONIC; Manufacturer PN: EEHZC1K330P; PART_NUMBER: 150-1298; Package Size: 10x10.2mm,SMD,RADIAL; Part Number: PANASONIC EEHZC1K330P; Rated Voltage: 80V; Tolerance: 20%
C37-C44 = CAP_P_ALT: CAP.,100uF,ALUM POLY HYB,25V,20%,6.3x7.7mm,D8,SMD,RADIAL,AEC-Q200; CLASS: DISCRETE; Dielectric Type: ALUM POLY HYB; Inventory Qty: 12960; Manufacturer: PANASONIC; Manufacturer PN: EEHZA1E101XP; PART_NUMBER: 150-2391; Package Size: 6.3x7.7mm,D8,SMD,RADIAL; Part Number: PANASONIC EEHZA1E101XP; Rated Voltage: 25V; Tolerance: 20%
C45-C48 C53-C55 C57-C59 C72-C75 C77 C78 C122-C125 = CAP: CAP.,2.2uF,X7R,100V,10%,1210; CLASS: DISCRETE; Dielectric Type: X7R; FPLIST: CC1210N,CC1210L,CC1210M; Inventory Qty: 48336; Manufacturer: MURATA; Manufacturer PN: GRM32ER72A225KA35L; PART_NUMBER: 150-3049; Package Size: 1210; Part Number: AVX 12101C225KAT2A; Rated Voltage: 100V; Tolerance: 10%
C49-C52 C90-C101 C134-C137 C142-C185 = CAP: CAP., OPTION, 1210; CLASS: DISCRETE; FPLIST: CC0805N,CC0805L,CC0805M; PART_NUMBER: 150-3035; Package Size: 1210; Package Type: SMD
C56 C64 C76 C79 = CAP: CAP.,0.1uF,X7R,25V,10%,0603,AEC-Q200; CLASS: DISCRETE; Dielectric Type: X7R; FPLIST: CC0603N,CC0603L,CC0603M; Inventory Qty: 5452; Manufacturer: AVX; Manufacturer PN: 06033C104K4T4A; PART_NUMBER: 150-0439; Package Size: 0603; Part Number: AVX 06033D224KAT2A; Rated Voltage: 25V; Tolerance: 10%
C60 C61 C80 C81 = CAP: CAP.,0.1uF,X7R,25V,10%,0603,AEC-Q200; CLASS: DISCRETE; Dielectric Type: X7R; FPLIST: CC0603N,CC0603L,CC0603M; Inventory Qty: 5452; Manufacturer: AVX; Manufacturer PN: 06033C104K4T4A; PART_NUMBER: 150-0439; Package Size: 0603; Part Number: OPTION; Rated Voltage: 25V; Tolerance: 10%
C63 C65 C68 C69 C82 C83 C86 C87 = CAP: CAP.,0.22uF,X7R,25V,10%,0603; CLASS: DISCRETE; Dielectric Type: X7R; FPLIST: CC0603N,CC0603L,CC0603M; Inventory Qty: 25529; Manufacturer: MURATA; Manufacturer PN: GRM188R71E224KA88D; PART_NUMBER: 150-0320; Package Size: 0603; Part Number: AVX 06033D224KAT2A; Rated Voltage: 25V; Tolerance: 10%
C66 C67 C84 C85 = CAP: CAP.,10uF,X7R,25V,10%,1210; CLASS: DISCRETE; Dielectric Type: X7R; FPLIST: CC1210N,CC1210L,CC1210M; Inventory Qty: 11823; Manufacturer: AVX; Manufacturer PN: 12103C106KAT2A; PART_NUMBER: 150-0282; Package Size: 1210; Part Number: MURATA GRM31CR71E106KA12L; Rated Voltage: 25V; Tolerance: 10%
C70 C71 C88 C89 = CAP: CAP.,1uF,X7R,25V,10%,0603,AEC-Q200; CLASS: DISCRETE; Dielectric Type: X7R; FPLIST: CC0603N,CC0603L,CC0603M; Inventory Qty: 53700; Manufacturer: MURATA; Manufacturer PN: GCM188R71E105KA64D; PART_NUMBER: 150-0291; Package Size: 0603; Part Number: AVX 06033D224KAT2A; Rated Voltage: 25V; Tolerance: 10%
C102 C103 = CAP_P: CAP.,5100uF,ALUM ELEC., 20% 35V RADIAL; CLASS: DISCRETE; Dielectric Type: ALUM ELEC.; Inventory Qty: 0; Manufacturer: Chemi-Con; Manufacturer PN: EKYC350ELL512MM30S; PART_NUMBER: Local_150-0991; Package Size: RADIAL,THT; Rated Voltage: 35V; Tolerance: 20%
C126-C133 = CAP_P_ALT: CAP.,100uF,ALUM POLY HYB,25V,20%,6.3x7.7mm,D8,SMD,RADIAL,AEC-Q200; BOM Notes: OPT; CLASS: DISCRETE; Dielectric Type: ALUM POLY HYB; Inventory Qty: 12960; Manufacturer: PANASONIC; Manufacturer PN: EEHZA1E101XP; PART_NUMBER: 150-2391; Package Size: 6.3x7.7mm,D8,SMD,RADIAL; Part Number: PANASONIC EEHZA1E101XP; Rated Voltage: 25V; Tolerance: 20%
D4-D7 = DIODE_SCHOTTKY_A_ALT: DIODE,SCHOTTKY,100V,1A,POWERDI-123; CLASS: DISCRETE; Inventory Qty: 15626; Manufacturer: DIODES INC.; Manufacturer PN: DFLS1100-7; Max Forward Current or Rated Power: 1A; PART_NUMBER: 210-0044; Package Size: POWERDI®123; Part Number: DIODES INC. DFLS1100-7; Rated Voltage or Zener Voltage: 100V
E16 = TESTPOINT_.219_MILL-MAX_2501: TEST POINT,TURRET,0.094" MTG. HOLE,PCB 0.062" THK; CLASS: IO; FPLIST: MILLMAX2501,MILLMAX2501_ALT1; Inventory Qty: 823526; Manufacturer: MILL-MAX; Manufacturer PN: 2501-2-00-80-00-00-07-0; PART_FIELD_01: VHIGH; PART_NUMBER: 260-0003; Part Number: MIIL-MAX 2501-2-00-80-00-00-07-0
E17 = TESTPOINT_.219_MILL-MAX_2501: TEST POINT,TURRET,0.094" MTG. HOLE,PCB 0.062" THK; CLASS: IO; FPLIST: MILLMAX2501,MILLMAX2501_ALT1; Inventory Qty: 823526; Manufacturer: MILL-MAX; Manufacturer PN: 2501-2-00-80-00-00-07-0; PART_FIELD_01: VLOW; PART_NUMBER: 260-0003; Part Number: MIIL-MAX 2501-2-00-80-00-00-07-0
J2 J10 = PEM-KFH_A: EVAL BOARD STUD HARDWARE SET, #10-32; 10th Part Field: 30V TO 75V; 11th Part Field: 11th???; 9th Part Field: VHIGH; CLASS: DISCRETE; Comments: CONSISTS OF QTY(1) STUD, 769-0012; QTY(1) RING LUG, 769-0013;QTY(2) HEX NUT,BRASS,761-0013; QTY(1) WASHER,#10 LOCK, 762-0021; Manufacturer: ANALOG DEVICES; Manufacturer PN: 720-0010; PART_NUMBER: 720-0010; Part Number: PEM KFH-032-10
J3 = PEM-KFH_A: EVAL BOARD STUD HARDWARE SET, #10-32; 10th Part Field: 30V UP TO 75V; 11th Part Field: 11th???; 9th Part Field: VLOW; CLASS: DISCRETE; Comments: CONSISTS OF QTY(1) STUD, 769-0012; QTY(1) RING LUG, 769-0013;QTY(2) HEX NUT,BRASS,761-0013; QTY(1) WASHER,#10 LOCK, 762-0021; Manufacturer: ANALOG DEVICES; Manufacturer PN: 720-0010; PART_NUMBER: 720-0010; Part Number: PEM KFH-032-10
J4 = PEM-KFH_A: EVAL BOARD STUD HARDWARE SET, #10-32; 10th Part Field: 14V / 120A; 11th Part Field: 11th???; 9th Part Field: VLOW; CLASS: DISCRETE; Comments: CONSISTS OF QTY(1) STUD, 769-0012; QTY(1) RING LUG, 769-0013;QTY(2) HEX NUT,BRASS,761-0013; QTY(1) WASHER,#10 LOCK, 762-0021; Manufacturer: ANALOG DEVICES; Manufacturer PN: 720-0010; PART_NUMBER: 720-0010; Part Number: PEM KFH-032-10
J5-J7 J11 = PEM-KFH_A: EVAL BOARD STUD HARDWARE SET, #10-32; 10th Part Field: 5 - 24V #; 11th Part Field: 11th???; 9th Part Field: GND; CLASS: DISCRETE; Comments: CONSISTS OF QTY(1) STUD, 769-0012; QTY(1) RING LUG, 769-0013;QTY(2) HEX NUT,BRASS,761-0013; QTY(1) WASHER,#10 LOCK, 762-0021; Manufacturer: ANALOG DEVICES; Manufacturer PN: 720-0010; PART_NUMBER: 720-0010; Part Number: PEM KFH-032-10
J8 = PEM-KFH_A: EVAL BOARD STUD HARDWARE SET, #10-32; 10th Part Field: 14V / 200A; 11th Part Field: 11th???; 9th Part Field: VLOW; CLASS: DISCRETE; Comments: CONSISTS OF QTY(1) STUD, 769-0012; QTY(1) RING LUG, 769-0013;QTY(2) HEX NUT,BRASS,761-0013; QTY(1) WASHER,#10 LOCK, 762-0021; Manufacturer: ANALOG DEVICES; Manufacturer PN: 720-0010; PART_NUMBER: 720-0010; Part Number: PEM KFH-032-10
J9 = PEM-KFH_A: EVAL BOARD STUD HARDWARE SET, #10-32; 10th Part Field: 14V / 200A; 11th Part Field: 11th???; 9th Part Field: GND; CLASS: DISCRETE; Comments: CONSISTS OF QTY(1) STUD, 769-0012; QTY(1) RING LUG, 769-0013;QTY(2) HEX NUT,BRASS,761-0013; QTY(1) WASHER,#10 LOCK, 762-0021; Manufacturer: ANALOG DEVICES; Manufacturer PN: 720-0010; PART_NUMBER: 720-0010; Part Number: PEM KFH-032-10
L1-L4 = IND: IND.,6.8uH,HIGH CURRENT,15%,30A,2.4mOHM,2818 SMD; CLASS: DISCRETE; FPLIST: WURTH-2818,WURTH-7443640680; Inventory Qty: 990; Manufacturer: WURTH ELEKTRONIK; Manufacturer PN: 7443640680; PART_NUMBER: 200-0492; Package Size: 2818 SMD; Tolerance: 15%
Q1-Q16 = 8P_N-CH_TYPE1A: MOSFET N-Ch 100V 90A TDSON-8; CLASS: DISCRETE; Manufacturer: Infineon Technologies; PART_NUMBER: Local_4692; Package Size: TDSON-8; Package Type: SMD/SMT; Polarity: N-Channel; Rated Power: 114 W; Rated Voltage: 100 V
R39 R44 R61 R64 = RES: RES.,1.69k OHMS,1%,1/10W,0603,AEC-Q200; CLASS: DISCRETE; FPLIST: CR0603N,CR0603L,CR0603M; Inventory Qty: 11723; Manufacturer: NIC; Manufacturer PN: NRC06F1691TRF; PART_NUMBER: 100-2797; Package Size: 0603; Rated Power: 1/10W; Temperature Coefficient: 100ppm/C; Tolerance: 1%
R40 R48 R70 R72 = RES: RES.,1.5k OHMS,1%,1/10W,0603; CLASS: DISCRETE; FPLIST: CR0603N,CR0603L,CR0603M; Inventory Qty: 13500; Manufacturer: NIC; Manufacturer PN: NRC06F1501TRF; PART_NUMBER: 100-0310; Package Size: 0603; Rated Power: 1/10W; Temperature Coefficient: 100ppm/C; Tolerance: 1%
R41 R47 R50 R54 R58 R60 R62 R63 R65 R71 R81 R82 = RES: RES.,0 OHM,1/10W,0603; CLASS: DISCRETE; FPLIST: CR0603N,CR0603L,CR0603M; Inventory Qty: 57380; Manufacturer: BOURNS; Manufacturer PN: CR0603-J/-000ELF; PART_NUMBER: 100-2621; Package Size: 0603; Part Number: VISHAY CRCW0603300RFKEA; Rated Power: 1/10W
R42 R45 R66 R67 = RES: RES.,3.3 OHMS,1%,1/10W,0603,AEC-Q200; CLASS: DISCRETE; FPLIST: CR0603N,CR0603L,CR0603M; Inventory Qty: 42849; Manufacturer: VISHAY; Manufacturer PN: CRCW06033R30FKEA; PART_NUMBER: 100-0639; Package Size: 0603; Rated Power: 1/10W; Temperature Coefficient: +/-100PPM; Tolerance: 1%
R46 R51 R68 R74 = RES: RES.,16.9k OHMS,1%,1/8W,0805,AEC-Q200; CLASS: DISCRETE; FPLIST: CR0805N,CR0805L,CR0805M; Inventory Qty: 5000; Manufacturer: STACKPOLE ELECTRONICS, INC.; Manufacturer PN: RMCF0805FT16K9; PART_NUMBER: 100-1656; Package Size: 0805; Part Number: VISHAY CRCW06034K99FKEA; Rated Power: 1/8W; Temperature Coefficient: +/-100ppm; Tolerance: 1%
R49 R55 R75 R76 = RES: RES.,100k OHMS,1%,1/10W,0603,AEC-Q200; CLASS: DISCRETE; FPLIST: CR0603N,CR0603L,CR0603M; Inventory Qty: 185604; Manufacturer: VISHAY; Manufacturer PN: CRCW0603100KFKEA; PART_NUMBER: 100-0343; Package Size: 0603; Part Number: VISHAY CRCW0603300RFKEA; Rated Power: 1/10W; Temperature Coefficient: +/-100ppm; Tolerance: 1%
R52 R57 R77 R79 = RES: RES.,10 OHMS,1%,1/10W,0603; CLASS: DISCRETE; FPLIST: CR0603N,CR0603L,CR0603M; Inventory Qty: 152750; Manufacturer: VISHAY; Manufacturer PN: CRCW060310R0FKEA; PART_NUMBER: 100-2306; Package Size: 0603; Part Number: VISHAY CRCW0603300RFKEA; Rated Power: 1/10W; Temperature Coefficient: 100ppm/C; Tolerance: 1%
RSNS1-RSNS4 = RES: RES.,0.001 OHMS,1%,3W,2512,AEC-Q200 LONG-SIDE TERM; CLASS: DISCRETE; FPLIST: SUSUMU-KRL6432,SUSUMU-KRL6432-4PIN,USER_ASSIGNED; Inventory Qty: 0; Manufacturer: SUSUMU; Manufacturer PN: KRL6432E-M-R001-J-T1; PART_NUMBER: 100-1892; Package Size: 2512; Rated Power: 3W; Temperature Coefficient: +/-150PPM; Tolerance: 1%
U1-U4 = LTC7060-MSE_1: IC,DC/DC CONVERTER,MSE-12; CLASS: IC; Inventory Qty: 0; Manufacturer: ANALOG DEVICES; Manufacturer PN: LTC7060EMSE#PBF; PART_NUMBER: LTC7060EMSE#PBF; Package Type: MSE-12
MP1-MP9 = BLANK_MECHANICAL_PART: STANDOFF,NYLON,SNAP-ON,0.25" (6.4mm); CLASS: DISCRETE; Inventory Qty: 227624; Manufacturer: KEYSTONE; Manufacturer PN: 8831; PART_NUMBER: 763-0006
PCB1 = BLANK_PCB_PART: BOM Notes: REV02; CLASS: DISCRETE; Inventory Qty: 0; PART_NUMBER: TMP-8225
Q17-Q32 = 9P_N-CH_TYPE1A: 80V 165A 2.9MOHM TOLL; CLASS: DISCRETE; Manufacturer: Infineon Technologies; Manufacturer PN: IAUT165N08S5N029ATMA2; PART_NUMBER: LOCAL-TMP-5455; Package Size: 8-PowerSFN; Package Type: Surface Mount; Rated Power: 167W (Tc)
T1 T2 = TDK-DS-P302376-A3-51-01: IND.,4.6uH,PWR,CUSTOM PRELIM; BOM Notes: OPT; CLASS: DISCRETE; Inventory Qty: 0; Manufacturer: TDK; PART_NUMBER: 200-0889

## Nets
12VAUX: C105.1 D8.2(A) E22.1 R85.2
GND: C3.2 C5.2 C6.2 C8.2 C16.2 C17.1 C18.1 C19.2 C20.2 C21.2 C22.2 C23.2 C24.2 C25.2 C26.2 C27.2 C28.2 C29.2 C30.2 C31.2 C32.2 C33.2 C34.2 C35.2 C36.2 C37.2 C38.2 C39.2 C40.2 C41.2 C42.2 C43.2 C44.2 C45.1 C46.1 C47.1 C48.1 C49.1 C50.1 C51.1 C52.1 C53.1 C54.1 C55.1 C57.1 C58.1 C59.1 C62.2 C66.1 C67.1 C68.1 C69.1 C70.1 C71.1 C72.1 C73.1 C74.1 C75.1 C77.1 C78.1 C84.1 C85.1 C86.1 C87.1 C88.1 C89.1 C90.1 C91.1 C92.1 C93.1 C94.1 C95.1 C96.1 C97.1 C98.1 C99.1 C100.1 C101.1 C102.2 C103.2 C104.2 C105.2 C106.2 C107.2 C108.2 C109.2 C110.2 C111.2 C112.2 C113.2 C114.2 C115.2 C116.2 C117.2 C118.2 C119.2 C120.2 C121.2 C122.1 C123.1 C124.1 C125.1 C126.2 C127.2 C128.2 C129.2 C130.2 C131.2 C132.2 C133.2 C134.2 C135.2 C136.2 C137.2 C142.2 C143.2 C144.2 C145.2 C146.2 C147.2 C148.2 C149.2 C150.2 C151.2 C152.2 C153.2 C154.2 C155.2 C156.2 C157.2 C158.2 C159.2 C160.2 C161.2 C162.2 C163.2 C164.2 C165.2 C166.2 C167.2 C168.2 C169.2 C170.2 C171.2 C172.2 C173.2 C174.2 C175.2 C176.2 C177.2 C178.2 C179.2 C180.2 C181.2 C182.2 C183.2 C184.2 C185.2 D3.2(A) E1.1 E2.1 E18.1 E19.1 E21.1 E23.1 J1.3(GND) J1.8(GND) J1.12(EEGND) J1.13(GND) J5.1(TP) J6.1(TP) J7.1(TP) J9.1(TP) J11.1(TP) JP1.4 JP2.3 JP4.2 Q3.1(S) Q3.2(S) Q3.3(S) Q4.1(S) Q4.2(S) Q4.3(S) Q7.1(S) Q7.2(S) Q7.3(S) Q8.1(S) Q8.2(S) Q8.3(S) Q11.1(S) Q11.2(S) Q11.3(S) Q12.1(S) Q12.2(S) Q12.3(S) Q15.1(S) Q15.2(S) Q15.3(S) Q16.1(S) Q16.2(S) Q16.3(S) Q21.2(S) Q21.3(S) Q21.4(S) Q21.5(S) Q21.6(S) Q21.7(S) Q21.8(S) Q22.2(S) Q22.3(S) Q22.4(S) Q22.5(S) Q22.6(S) Q22.7(S) Q22.8(S) Q23.2(S) Q23.3(S) Q23.4(S) Q23.5(S) Q23.6(S) Q23.7(S) Q23.8(S) Q24.2(S) Q24.3(S) Q24.4(S) Q24.5(S) Q24.6(S) Q24.7(S) Q24.8(S) Q29.2(S) Q29.3(S) Q29.4(S) Q29.5(S) Q29.6(S) Q29.7(S) Q29.8(S) Q30.2(S) Q30.3(S) Q30.4(S) Q30.5(S) Q30.6(S) Q30.7(S) Q30.8(S) Q31.2(S) Q31.3(S) Q31.4(S) Q31.5(S) Q31.6(S) Q31.7(S) Q31.8(S) Q32.2(S) Q32.3(S) Q32.4(S) Q32.5(S) Q32.6(S) Q32.7(S) Q32.8(S) R10.1 R29.1 R37.2 R38.2 R58.2 R60.2 R81.2 R82.2 SW1.6 U1.7(BGRTN) U1.13(SGND) U2.7(BGRTN) U2.13(SGND) U3.7(BGRTN) U3.13(SGND) U4.7(BGRTN) U4.13(SGND) U6.1(A0) U6.2(A1) U6.3(A2) U6.4(GND)
GNDSIGNAL: C1.2 C2.1 C4.1 C7.1 C9.1 C10.1 C11.1 C14.1 C15.1 E8.1 R4.2 R5.2 R13.1 R14.1 R18.1 R19.1 R27.2 R28.2 U5.4(SGND) U5.33(SGND) U5.49(GND)
V5: C2.2 C17.2 JP1.1 JP3.2 R6.2 R8.2 R20.2 R22.2 R23.2 R30.2 R33.2 R83.2 U5.7(V5)
3r3V_5V: C18.2 J1.2(3.3V_or_5V) JP3.3 R24.1
BG1: Q3.4(G) Q4.4(G) Q21.1(G) Q22.1(G) R59.2
BG2: Q7.4(G) Q8.4(G) Q29.1(G) Q30.1(G) R80.2
BG3: Q11.4(G) Q12.4(G) Q23.1(G) Q24.1(G) R56.2
BG4: Q15.4(G) Q16.4(G) Q31.1(G) Q32.1(G) R78.2
CSB: E12.1 R25.1 U5.27(CSB)
DRVCC: C70.2 C71.2 C88.2 C89.2 C104.1 D4.2(A) D5.2(A) D6.2(A) D7.2(A) R52.2 R57.2 R77.2 R79.2 R84.2 R85.1 U1.6(BGVcc) U2.6(BGVcc) U3.6(BGVcc) U4.6(BGVcc)
DRVCC7872: C5.1 R84.1 U5.34(DRVCC)
LN1: L1.2 R48.1 RSNS1.1 T1.1
LN2: L2.2 R72.1 RSNS2.1 T1.2
LN3: L3.2 R40.1 RSNS3.1 T2.1
LN4: L4.2 R70.1 RSNS4.1 T2.2
PGOOD: E20.1 R6.1 U5.22(PGOOD)
PWM1: R41.1 U5.21(PWM1)
PWM2: R62.1 U5.23(PWM2)
PWM3: R47.1 U5.24(PWM3)
PWM4: R65.1 U5.26(PWM4)
PWMEN: E15.1 R30.1 R50.1 R54.1 R63.1 R71.1 U5.20(PWMEN)
RUN: JP2.2 JP5.2 JP5.3 U5.19(RUN)
SAC1: C64.1 C140.1 R39.2 R51.2 R94.1 U5.13(SNSA1+)
SAC2: C79.2 C138.1 R64.1 R68.2 R96.1 U5.18(SNSA2+)
SAC3: C56.1 C141.1 R44.2 R46.2 R98.1 U5.43(SNSA3+)
SAC4: C76.2 C139.1 R61.1 R74.2 R100.1 U5.48(SNSA4+)
SCL: E10.1 R21.1 U5.30(SCLK)
SDC1: C61.2 R48.2 R94.2 R95.1 U5.15(SNSD1+)
SDC2: C81.1 R72.2 R96.2 R97.1 U5.16(SNSD2+)
SDC3: C60.2 R40.2 R98.2 R99.1 U5.45(SNSD3+)
SDC4: C80.1 R70.2 R100.2 R101.1 U5.46(SNSD4+)
SDI: E13.1 R26.1 U5.29(SDI)
SDO: E11.1 J1.5(MISO) R23.1 R24.2 U5.28(SDO)
SN1: C61.1 C64.2 R39.1 R86.2 R95.2 U5.14(SNS1-)
SN2: C79.1 C81.2 R64.2 R88.2 R97.2 U5.17(SNS2-)
SN3: C56.2 C60.1 R44.1 R87.2 R99.2 U5.44(SNS3-)
SN4: C76.1 C80.2 R61.2 R89.2 R101.2 U5.47(SNS4-)
SW1: C63.1 L1.1 Q1.1(S) Q1.2(S) Q1.3(S) Q2.1(S) Q2.2(S) Q2.3(S) Q3.5(D) Q3.6(D) Q3.7(D) Q3.8(D) Q4.5(D) Q4.6(D) Q4.7(D) Q4.8(D) Q17.2(S) Q17.3(S) Q17.4(S) Q17.5(S) Q17.6(S) Q17.7(S) Q17.8(S) Q18.2(S) Q18.3(S) Q18.4(S) Q18.5(S) Q18.6(S) Q18.7(S) Q18.8(S) Q21.9(D) Q22.9(D) R51.1 R90.1 T1.4 U1.10(SW)
SW2: C83.1 L2.1 Q5.1(S) Q5.2(S) Q5.3(S) Q6.1(S) Q6.2(S) Q6.3(S) Q7.5(D) Q7.6(D) Q7.7(D) Q7.8(D) Q8.5(D) Q8.6(D) Q8.7(D) Q8.8(D) Q25.2(S) Q25.3(S) Q25.4(S) Q25.5(S) Q25.6(S) Q25.7(S) Q25.8(S) Q26.2(S) Q26.3(S) Q26.4(S) Q26.5(S) Q26.6(S) Q26.7(S) Q26.8(S) Q29.9(D) Q30.9(D) R68.1 R92.1 T1.3 U2.10(SW)
SW3: C65.1 L3.1 Q9.1(S) Q9.2(S) Q9.3(S) Q10.1(S) Q10.2(S) Q10.3(S) Q11.5(D) Q11.6(D) Q11.7(D) Q11.8(D) Q12.5(D) Q12.6(D) Q12.7(D) Q12.8(D) Q19.2(S) Q19.3(S) Q19.4(S) Q19.5(S) Q19.6(S) Q19.7(S) Q19.8(S) Q20.2(S) Q20.3(S) Q20.4(S) Q20.5(S) Q20.6(S) Q20.7(S) Q20.8(S) Q23.9(D) Q24.9(D) R46.1 R91.1 T2.4 U3.10(SW)
SW4: C82.1 L4.1 Q13.1(S) Q13.2(S) Q13.3(S) Q14.1(S) Q14.2(S) Q14.3(S) Q15.5(D) Q15.6(D) Q15.7(D) Q15.8(D) Q16.5(D) Q16.6(D) Q16.7(D) Q16.8(D) Q27.2(S) Q27.3(S) Q27.4(S) Q27.5(S) Q27.6(S) Q27.7(S) Q27.8(S) Q28.2(S) Q28.3(S) Q28.4(S) Q28.5(S) Q28.6(S) Q28.7(S) Q28.8(S) Q31.9(D) Q32.9(D) R74.1 R93.1 T2.3 U4.10(SW)
TG1: Q1.4(G) Q2.4(G) Q17.1(G) Q18.1(G) R53.2
TG2: Q5.4(G) Q6.4(G) Q25.1(G) Q26.1(G) R69.2
TG3: Q9.4(G) Q10.4(G) Q19.1(G) Q20.1(G) R43.2
TG4: Q13.4(G) Q14.4(G) Q27.1(G) Q28.1(G) R73.2
VHIGH: C21.1 C22.1 C23.1 C24.1 C25.1 C26.1 C27.1 C28.1 C29.1 C30.1 C31.1 C32.1 C33.1 C34.1 C35.1 C36.1 C45.2 C46.2 C47.2 C48.2 C49.2 C50.2 C51.2 C52.2 C53.2 C54.2 C55.2 C57.2 C58.2 C59.2 C72.2 C73.2 C74.2 C75.2 C77.2 C78.2 C90.2 C91.2 C92.2 C93.2 C94.2 C95.2 C96.2 C97.2 C98.2 C99.2 C100.2 C101.2 C106.1 C107.1 C108.1 C109.1 C110.1 C111.1 C112.1 C113.1 C114.1 C115.1 C116.1 C117.1 C118.1 C119.1 C120.1 C121.1 C134.1 C135.1 C136.1 C137.1 C142.1 C143.1 C144.1 C145.1 C146.1 C147.1 C148.1 C149.1 C150.1 C151.1 C152.1 C153.1 C154.1 C155.1 C156.1 C157.1 C158.1 C159.1 C160.1 C161.1 C162.1 C163.1 C164.1 C165.1 C166.1 C167.1 C168.1 C169.1 C170.1 C171.1 C172.1 C173.1 C174.1 C175.1 C176.1 C177.1 C178.1 C179.1 C180.1 C181.1 C182.1 C183.1 C184.1 C185.1 D9.2(A) E16.1 J2.1(TP) J10.1(TP) Q1.5(D) Q1.6(D) Q1.7(D) Q1.8(D) Q2.5(D) Q2.6(D) Q2.7(D) Q2.8(D) Q5.5(D) Q5.6(D) Q5.7(D) Q5.8(D) Q6.5(D) Q6.6(D) Q6.7(D) Q6.8(D) Q9.5(D) Q9.6(D) Q9.7(D) Q9.8(D) Q10.5(D) Q10.6(D) Q10.7(D) Q10.8(D) Q13.5(D) Q13.6(D) Q13.7(D) Q13.8(D) Q14.5(D) Q14.6(D) Q14.7(D) Q14.8(D) Q17.9(D) Q18.9(D) Q19.9(D) Q20.9(D) Q25.9(D) Q26.9(D) Q27.9(D) Q28.9(D) R1.1 R2.1 R3.2 R15.2 R35.1
VLOW: C37.1 C38.1 C39.1 C40.1 C41.1 C42.1 C43.1 C44.1 C62.1 C66.2 C67.2 C84.2 C85.2 C102.1 C103.1 C122.2 C123.2 C124.2 C125.2 C126.1 C127.1 C128.1 C129.1 C130.1 C131.1 C132.1 C133.1 D1.2(A) E17.1 J3.1(TP) J4.1(TP) J8.1(TP) R11.2 R16.1 R36.1 R86.1 R87.1 R88.1 R89.1 RSNS1.2 RSNS2.2 RSNS3.2 RSNS4.2
N19599504: C3.1 D8.1(C) D9.1(C) R3.1 U5.36(VHIGH)
N19632194: C4.2 R7.2 U5.5(ITHHIGH)
N19643876: C9.2 R9.1
N19643878: C10.2 R9.2 U5.3(ITHLOW)
N19716351: R13.2 U5.41(FREQ)
N19723679: E4.1 R83.1 U5.40(SYNC)
N19741175: E9.1 SW1.5 U5.42(BUCK)
N20240653: JP1.2 JP1.3 U5.39(MODE)
N20387706: R22.1 R29.2 U5.32(DRVSET)
N20417031: C11.2 U5.1(SS)
N20536523: C15.2 E7.1 SW1.2 U5.9(SETCUR)
N21083681: R16.2 R18.2 U5.12(OVLOW)
N21963039: C14.2 E6.1 U5.8(IMON)
N21975323: E14.1 R33.1 U5.25(\\\\\\\\\\FAULT)
N22044941: R45.1 U3.12(BST)
N22044944: C65.2 D5.1(C) R45.2
N22263490: R1.2 R4.1 U5.11(UVHIGH)
N22379941: R43.1 U3.11(TG)
N22380043: C68.2 R49.2 R52.1 U3.5(Vcc)
N22380641: R58.1 U3.4(DT)
N22389376: R60.1 U1.4(DT)
N22389391: R42.1 U1.12(BST)
N22389401: C63.2 D4.1(C) R42.2
N22389409: C69.2 R55.2 R57.1 U1.5(Vcc)
N22389462: R53.1 U1.11(TG)
N22395761: R82.1 U2.4(DT)
N22395776: R67.1 U2.12(BST)
N22395778: C83.2 D7.1(C) R67.2
N22395792: C87.2 R76.2 R79.1 U2.5(Vcc)
N22395837: R69.1 U2.11(TG)
N22398181: R81.1 U4.4(DT)
N22398196: R66.1 U4.12(BST)
N22398198: C82.2 D6.1(C) R66.2
N22398212: C86.2 R75.2 R77.1 U4.5(Vcc)
N22398257: R73.1 U4.11(TG)
N22409295: C6.1 C8.1 D1.1(C) D2.1(C) D3.1(C) U5.31(EXTVCC)
N22413112: E5.1 U5.38(CLKOUT)
N22413677: J1.4(SCK/SCL) R21.2
N22413687: J1.6(CS) R25.2
N22413689: J1.7(MOSI/SDA) R26.2
N22421972: C12.2 R12.2 R14.2 U5.2(VFBLOW)
N22421975: C12.1 R11.1 R12.1
N22422510: C13.2 R17.2 R19.2 U5.6(VFBHIGH)
N22422512: C13.1 R15.1 R17.1
N22515467: R55.1 U1.3(\\~{FLT})
N22517608: R76.1 U2.3(\\~{FLT})
N22535148: R49.1 U3.3(\\~{FLT})
N22535990: R75.1 U4.3(\\~{FLT})
N22617523: R41.2 U1.1(PWM)
N22617555: R50.2 U1.2(EN)
N22617620: R47.2 U3.1(PWM)
N22617651: R54.2 U3.2(EN)
N22617690: R62.2 U2.1(PWM)
N22617743: R63.2 U2.2(EN)
N22617915: R65.2 U4.1(PWM)
N22617963: R71.2 U4.2(EN)
N22621334: R8.1 R10.2 U5.37(ILIM)
N22624600: J1.11(EESCL) R31.1 U6.6(SCL)
N22624602: JP4.1 R32.1 U6.7(WP)
N22624620: J1.9(EESDA) R34.1 U6.5(SDA)
N22624638: C16.1 J1.10(EEVCC) R31.2 R32.2 R34.2 U6.8(VCC)
N22752069: R27.1 SW1.3
N22752195: R28.1 SW1.1
N23057774: C19.1 JP5.1 R35.2 R37.1
N23057807: C20.1 JP5.4 R36.2 R38.1
N23058673: R20.1 SW1.4
N23058914: R80.1 U2.8(BG)
N23060209: R59.1 U1.8(BG)
N23060271: R56.1 U3.8(BG)
N23060941: R78.1 U4.8(BG)
N23067719: C7.2 R7.1
N23102436: D2.2(A) E3.1
N23109610: C1.1 R2.2 R5.1 U5.10(OVHIGH)
N23287221: C138.2 R90.2
N23287460: C139.2 R91.2
N23288373: C140.2 R92.2
N23288381: C141.2 R93.2

Not connected (* = marked no-connect by the designer): J1 1(V+) 14(GPIO_1); JP2 1*; JP3 1*; JP4 3; U1 9(NC); U2 9(NC); U3 9(NC); U4 9(NC); U5 35(NC)

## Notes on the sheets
sheet 1
- To program the LTC7872
  with the DC2026C when
  the board is not powered,
  stuff diode at D9 and
  remove R3.
- For VHIGH > 100V:
  1. Connect external 12V supply to 12VAUX.
  2. Remove R3.
  3. Stuff D8.
  4. Replace the LTC7060 with the LTC7063.
- For IDRVCC > 150mA:
  1. Connect external 12V supply to 12VAUX.
  2. Remove 0 Ohm jumper from DRVCC7872 to DRVCC.
  3. Stuff 0 Ohm jumper from 12VAUX to DRVCC.
- Note:
  ILIM setting is V5:
  Vsense(max) = 62.5mV typical with Rsense
- BUCK: BURST
  BOOST: P.S.
- Fsw = 150kHz, typical
- EXTERNAL BIAS
  FOR LTC7872
  FROM LINDUINO
- OPT
- TO LINDUINO DC2026C
- IDENTITY EEPROM
- (manually connect on L5)
- RUN pin
  UVLO circuits
- NOTE: UNLESS OTHERWISE SPECIFIED
- 1.  ALL RESISTORS AND CAPACITORS ARE 0603.
sheet 2
- BOOST:
  48V / 34A @ 14VLOW
- Q9,Q10: BSC070N10NS3GATMA1
  Q11,Q12: BSC070N10NS3GATMA1
- Q1,Q2: BSC070N10NS3GATMA1
  Q3,Q4: BSC070N10NS3GATMA1
- Q13,Q14: BSC070N10NS3GATMA1
  Q15,Q16: BSC070N10NS3GATMA1
- Q5,Q6: BSC070N10NS3GATMA1
  Q7,Q8: BSC070N10NS3GATMA1
sheet 3
- Q17-Q32
- PCA ADDITIONAL PARTS
